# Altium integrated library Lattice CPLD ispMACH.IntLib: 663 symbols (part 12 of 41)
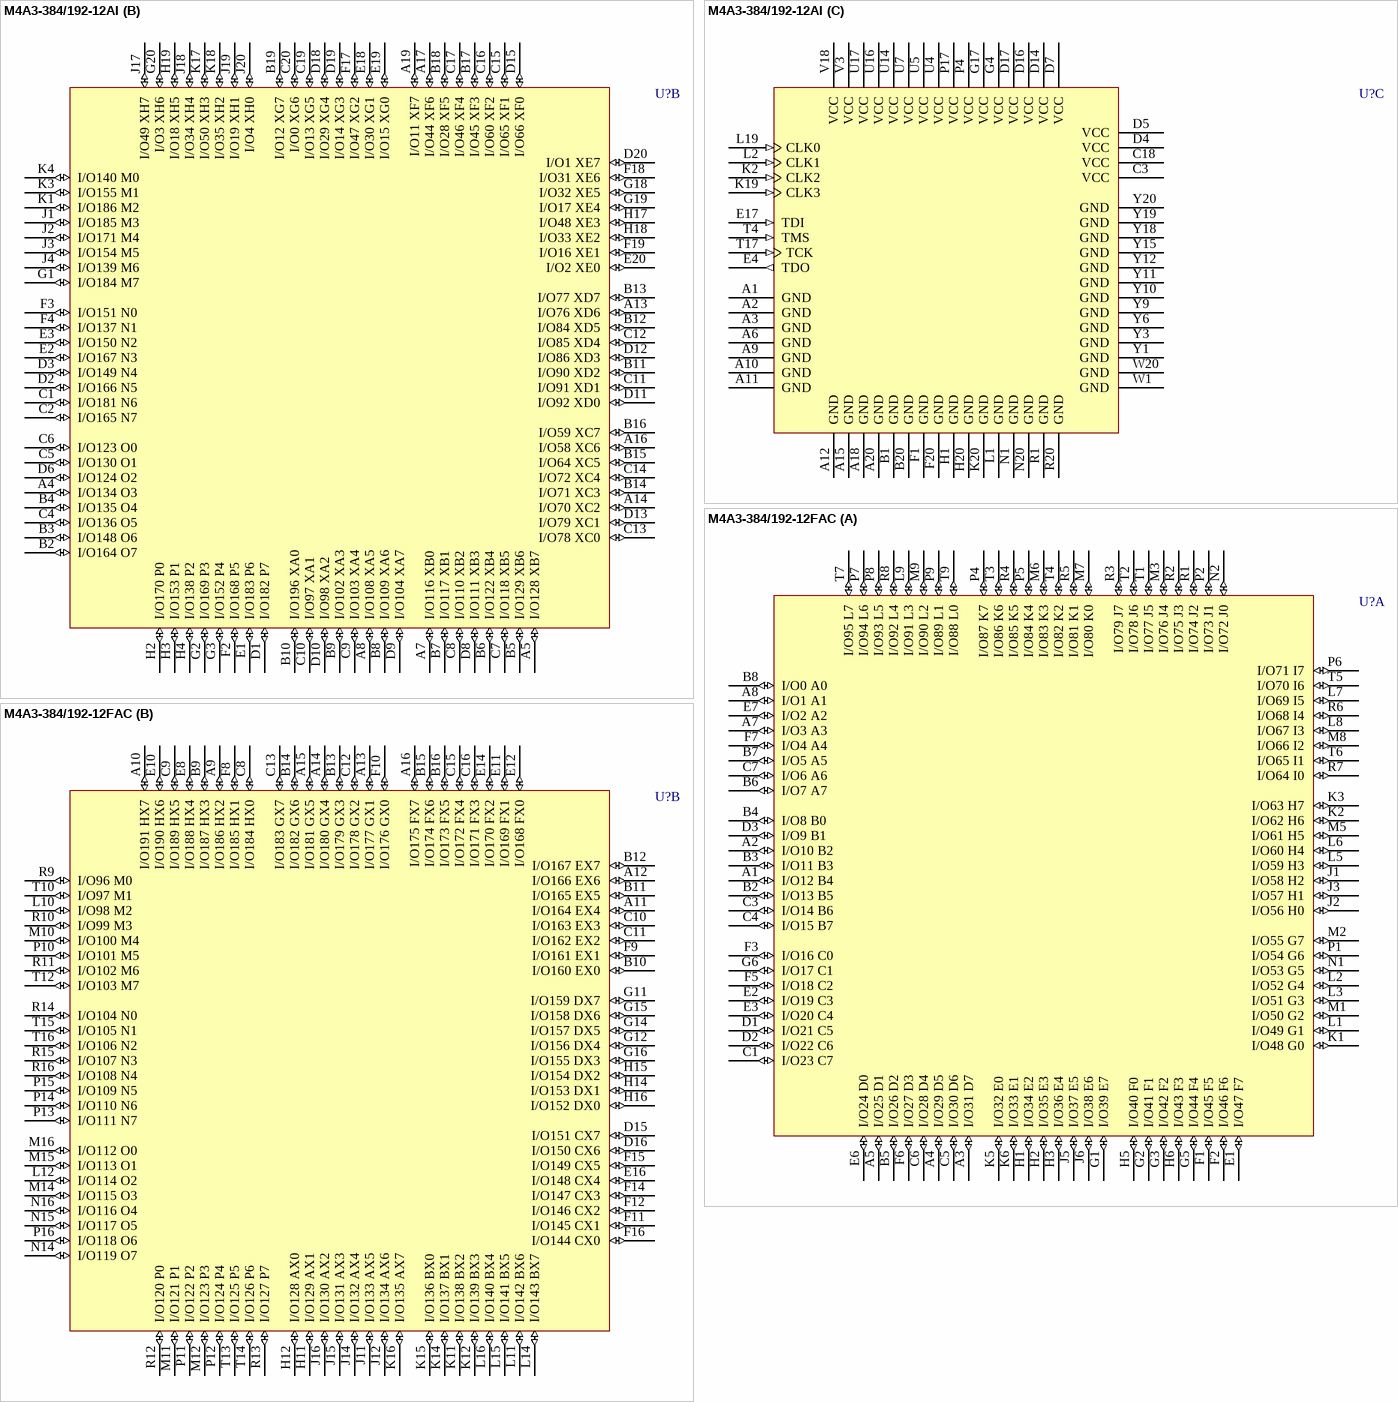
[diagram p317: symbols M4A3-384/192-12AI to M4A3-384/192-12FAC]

## M4A3-384/192-12AI
designator U?
High-Performance EE CMOS In-System Programmable Logic
footprint SBGA256 (BGA, 256-Leads, Body 27x27mm, Pitch 1.27mm)
3D model M4A3-SBGA256 (256-Ball Super Ball Grid Array (SBGA256))
part A pins: L3 I/O156 L4 (io), L4 I/O141 L3 (io), L17 I/O51 A1 (io), L18 I/O36 A0 (io), L20 I/O5 A2 (io), M1 I/O187 L1 (io), M2 I/O172 L0 (io), M3 I/O157 L5 (io), M4 I/O142 L6 (io), M17 I/O52 A6 (io), M18 I/O37 A5 (io), M19 I/O20 A3 (io), M20 I/O6 A4 (io), N2 I/O173 L7 (io), N3 I/O158 I0 (io), N4 I/O143 I5 (io), N17 I/O53 D1 (io), N18 I/O38 D0 (io), N19 I/O21 A7 (io), P1 I/O188 L2 (io), P2 I/O174 I1 (io), P3 I/O159 I4 (io), P18 I/O39 D4 (io), P19 I/O22 D3 (io), P20 I/O7 D2 (io), R2 I/O175 I3 (io), R3 I/O160 K0 (io), R4 I/O144 K5 (io), R17 I/O54 D7 (io), R18 I/O40 D6 (io), R19 I/O23 D5 (io), T1 I/O189 I2 (io), T2 I/O176 K1 (io), T3 I/O161 K4 (io), T18 I/O41 B7 (io), T19 I/O24 B0 (io), T20 I/O8 B3 (io), U1 I/O190 I6 (io), U2 I/O177 K2 (io), U3 I/O162 K7 (io), U6 I/O125 J1 (io), U8 I/O112 G0 (io), U9 I/O105 H5 (io), U10 I/O99 H2 (io), U11 I/O93 E2 (io), U12 I/O87 E5 (io), U13 I/O80 F0 (io), U15 I/O67 C0 (io), U18 I/O42 B6 (io), U19 I/O25 B1 (io), U20 I/O9 B4 (io), V1 I/O191 I7 (io), V2 I/O178 K3 (io), V4 I/O145 J5 (io), V5 I/O131 J2 (io), V6 I/O126 J0 (io), V7 I/O119 G4 (io), V8 I/O113 G1 (io), V9 I/O106 H4 (io), V10 I/O100 H1 (io), V11 I/O94 E1 (io), V12 I/O88 E4 (io), V13 I/O81 F1 (io), V14 I/O73 F4 (io), V15 I/O68 C1 (io), V16 I/O61 C2 (io), V17 I/O55 C5 (io), V19 I/O26 B2 (io), V20 I/O10 B5 (io), W2 I/O179 J7 (io), W3 I/O163 J6 (io), W4 I/O146 J4 (io), W5 I/O132 G7 (io), W6 I/O127 G5 (io), W7 I/O120 G3 (io), W8 I/O114 H7 (io), W9 I/O107 H3 (io), W10 I/O101 H0 (io), W11 I/O95 E0 (io), W12 I/O89 E3 (io), W13 I/O82 E7 (io), W14 I/O74 F3 (io), W15 I/O69 F5 (io), W16 I/O62 F7 (io), W17 I/O56 C3 (io), W18 I/O43 C6 (io), W19 I/O27 C7 (io), Y2 I/O180 K6 (io), Y4 I/O147 J3 (io), Y5 I/O133 G6 (io), Y7 I/O121 G2 (io), Y8 I/O115 H6 (io), Y13 I/O83 E6 (io), Y14 I/O75 F2 (io), Y16 I/O63 F6 (io), Y17 I/O57 C4 (io)
part B pins: A4 I/O134 O3 (io), A5 I/O128 XB7 (io), A7 I/O116 XB0 (io), A8 I/O108 XA5 (io), A13 I/O76 XD6 (io), A14 I/O70 XC2 (io), A16 I/O58 XC6 (io), A17 I/O44 XF6 (io), A19 I/O11 XF7 (io), B2 I/O164 O7 (io), B3 I/O148 O6 (io), B4 I/O135 O4 (io), B5 I/O129 XB6 (io), B6 I/O122 XB4 (io), B7 I/O117 XB1 (io), B8 I/O109 XA6 (io), B9 I/O102 XA3 (io), B10 I/O196 XA0 (io), B11 I/O90 XD2 (io), B12 I/O84 XD5 (io), B13 I/O77 XD7 (io), B14 I/O71 XC3 (io), B15 I/O64 XC5 (io), B16 I/O59 XC7 (io), B17 I/O45 XF3 (io), B18 I/O28 XF5 (io), B19 I/O12 XG7 (io), C1 I/O181 N6 (io), C2 I/O165 N7 (io), C4 I/O136 O5 (io), C5 I/O130 O1 (io), C6 I/O123 O0 (io), C7 I/O118 XB5 (io), C8 I/O110 XB2 (io), C9 I/O103 XA4 (io), C10 I/O97 XA1 (io), C11 I/O91 XD1 (io), C12 I/O85 XD4 (io), C13 I/O78 XC0 (io), C14 I/O72 XC4 (io), C15 I/O65 XF1 (io), C16 I/O60 XF2 (io), C17 I/O46 XF4 (io), C19 I/O13 XG5 (io), C20 I/O0 XG6 (io), D1 I/O182 P7 (io), D2 I/O166 N5 (io), D3 I/O149 N4 (io), D6 I/O124 O2 (io), D8 I/O111 XB3 (io), D9 I/O104 XA7 (io), D10 I/O98 XA2 (io), D11 I/O92 XD0 (io), D12 I/O86 XD3 (io), D13 I/O79 XC1 (io), D15 I/O66 XF0 (io), D18 I/O29 XG4 (io), D19 I/O14 XG3 (io), D20 I/O1 XE7 (io), E1 I/O183 P6 (io), E2 I/O167 N3 (io), E3 I/O150 N2 (io), E18 I/O30 XG1 (io), E19 I/O15 XG0 (io), E20 I/O2 XE0 (io), F2 I/O168 P5 (io), F3 I/O151 N0 (io), F4 I/O137 N1 (io), F17 I/O47 XG2 (io), F18 I/O31 XE6 (io), F19 I/O16 XE1 (io), G1 I/O184 M7 (io), G2 I/O169 P3 (io), G3 I/O152 P4 (io), G18 I/O32 XE5 (io), G19 I/O17 XE4 (io), G20 I/O3 XH6 (io), H2 I/O170 P0 (io), H3 I/O153 P1 (io), H4 I/O138 P2 (io), H17 I/O48 XE3 (io), H18 I/O33 XE2 (io), H19 I/O18 XH5 (io), J1 I/O185 M3 (io), J2 I/O171 M4 (io), J3 I/O154 M5 (io), J4 I/O139 M6 (io), J17 I/O49 XH7 (io), J18 I/O34 XH4 (io), J19 I/O19 XH1 (io), J20 I/O4 XH0 (io), K1 I/O186 M2 (io), K3 I/O155 M1 (io), K4 I/O140 M0 (io), K17 I/O50 XH3 (io), K18 I/O35 XH2 (io)
part C pins: A1 GND (power), A2 GND (power), A3 GND (power), A6 GND (power), A9 GND (power), A10 GND (power), A11 GND (power), A12 GND (power), A15 GND (power), A18 GND (power), A20 GND (power), B1 GND (power), B20 GND (power), C3 VCC (power), C18 VCC (power), D4 VCC (power), D5 VCC (power), D7 VCC (power), D14 VCC (power), D16 VCC (power), D17 VCC (power), E4 TDO (out), E17 TDI (in), F1 GND (power), F20 GND (power), G4 VCC (power), G17 VCC (power), H1 GND (power), H20 GND (power), K2 CLK2 (in), K19 CLK3 (in), K20 GND (power), L1 GND (power), L2 CLK1 (in), L19 CLK0 (in), N1 GND (power), N20 GND (power), P4 VCC (power), P17 VCC (power), R1 GND (power), R20 GND (power), T4 TMS (in), T17 TCK (in), U4 VCC (power), U5 VCC (power), U7 VCC (power), U14 VCC (power), U16 VCC (power), U17 VCC (power), V3 VCC (power), V18 VCC (power), W1 GND (power), W20 GND (power), Y1 GND (power), Y3 GND (power), Y6 GND (power), Y9 GND (power), Y10 GND (power), Y11 GND (power), Y12 GND (power), Y15 GND (power), Y18 GND (power), Y19 GND (power), Y20 GND (power)

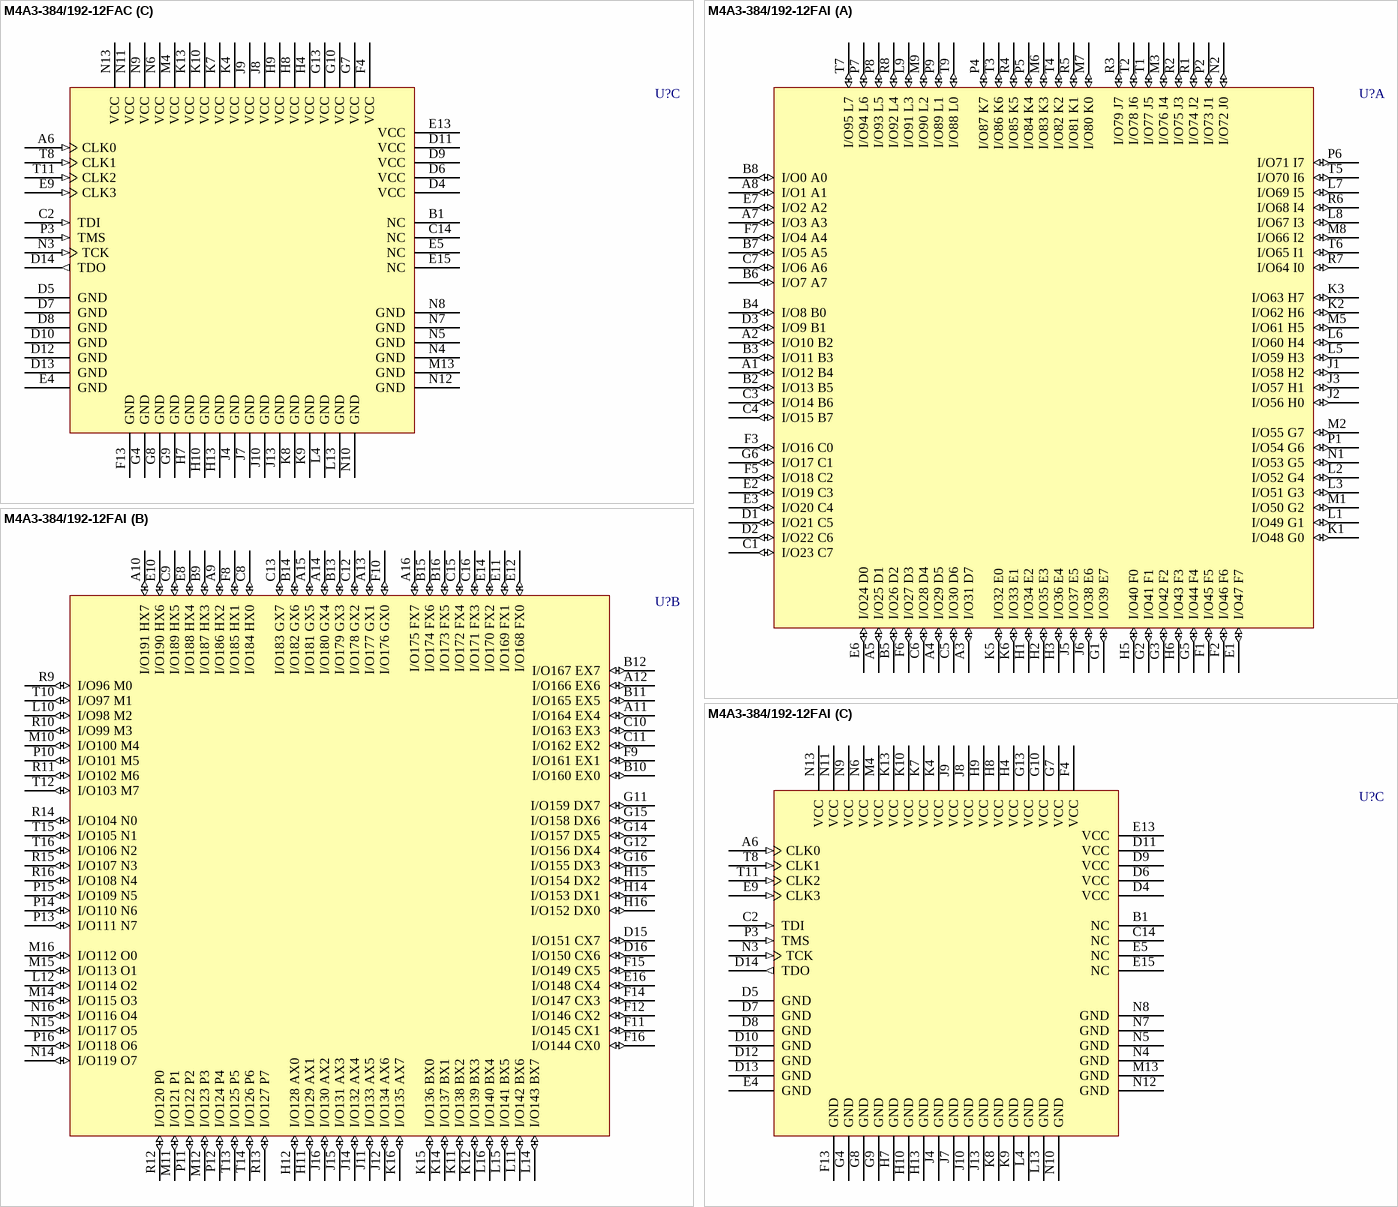
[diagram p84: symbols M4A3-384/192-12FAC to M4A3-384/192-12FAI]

## M4A3-384/192-12FAC
designator U?
High-Performance EE CMOS In-System Programmable Logic
footprint fpBGA256 (BGA, 256-Leads, Body 17x17mm, Pitch 1mm)
3D model M4A3-fpBGA256 (256-Ball Fine Pitch Ball Grid Array (fpBGA256))
part A pins: A1 I/O12 B4 (io), A2 I/O10 B2 (io), A3 I/O31 D7 (io), A4 I/O29 D5 (io), A5 I/O25 D1 (io), A7 I/O3 A3 (io), A8 I/O1 A1 (io), B2 I/O13 B5 (io), B3 I/O11 B3 (io), B4 I/O8 B0 (io), B5 I/O26 D2 (io), B6 I/O7 A7 (io), B7 I/O5 A5 (io), B8 I/O0 A0 (io), C1 I/O23 C7 (io), C3 I/O14 B6 (io), C4 I/O15 B7 (io), C5 I/O30 D6 (io), C6 I/O28 D4 (io), C7 I/O6 A6 (io), D1 I/O21 C5 (io), D2 I/O22 C6 (io), D3 I/O9 B1 (io), E1 I/O47 F7 (io), E2 I/O19 C3 (io), E3 I/O20 C4 (io), E6 I/O24 D0 (io), E7 I/O2 A2 (io), F1 I/O45 F5 (io), F2 I/O46 F6 (io), F3 I/O16 C0 (io), F5 I/O18 C2 (io), F6 I/O27 D3 (io), F7 I/O4 A4 (io), G1 I/O39 E7 (io), G2 I/O41 F1 (io), G3 I/O42 F2 (io), G5 I/O44 F4 (io), G6 I/O17 C1 (io), H1 I/O34 E2 (io), H2 I/O35 E3 (io), H3 I/O36 E4 (io), H5 I/O40 F0 (io), H6 I/O43 F3 (io), J1 I/O58 H2 (io), J2 I/O56 H0 (io), J3 I/O57 H1 (io), J5 I/O37 E5 (io), J6 I/O38 E6 (io), K1 I/O48 G0 (io), K2 I/O62 H6 (io), K3 I/O63 H7 (io), K5 I/O32 E0 (io), K6 I/O33 E1 (io), L1 I/O49 G1 (io), L2 I/O52 G4 (io), L3 I/O51 G3 (io), L5 I/O59 H3 (io), L6 I/O60 H4 (io), L7 I/O69 I5 (io), L8 I/O67 I3 (io), L9 I/O91 L3 (io), M1 I/O50 G2 (io), M2 I/O55 G7 (io), M3 I/O76 J4 (io), M5 I/O61 H5 (io), M6 I/O83 K3 (io), M7 I/O80 K0 (io), M8 I/O66 I2 (io), M9 I/O90 L2 (io), N1 I/O53 G5 (io), N2 I/O72 J0 (io), P1 I/O54 G6 (io), P2 I/O73 J1 (io), P4 I/O87 K7 (io), P5 I/O84 K4 (io), P6 I/O71 I7 (io), P7 I/O94 L6 (io), P8 I/O93 L5 (io), P9 I/O89 L1 (io), R1 I/O74 J2 (io), R2 I/O75 J3 (io), R3 I/O79 J7 (io), R4 I/O85 K5 (io), R5 I/O81 K1 (io), R6 I/O68 I4 (io), R7 I/O64 I0 (io), R8 I/O92 L4 (io), T1 I/O77 J5 (io), T2 I/O78 J6 (io), T3 I/O86 K6 (io), T4 I/O82 K2 (io), T5 I/O70 I6 (io), T6 I/O65 I1 (io), T7 I/O95 L7 (io), T9 I/O88 L0 (io)
part B pins: A9 I/O186 HX2 (io), A10 I/O191 HX7 (io), A11 I/O164 EX4 (io), A12 I/O166 EX6 (io), A13 I/O177 GX1 (io), A14 I/O180 GX4 (io), A15 I/O181 GX5 (io), A16 I/O175 FX7 (io), B9 I/O187 HX3 (io), B10 I/O160 EX0 (io), B11 I/O165 EX5 (io), B12 I/O167 EX7 (io), B13 I/O179 GX3 (io), B14 I/O182 GX6 (io), B15 I/O174 FX6 (io), B16 I/O173 FX5 (io), C8 I/O184 HX0 (io), C9 I/O189 HX5 (io), C10 I/O163 EX3 (io), C11 I/O162 EX2 (io), C12 I/O178 GX2 (io), C13 I/O183 GX7 (io), C15 I/O172 FX4 (io), C16 I/O171 FX3 (io), D15 I/O151 CX7 (io), D16 I/O150 CX6 (io), E8 I/O188 HX4 (io), E10 I/O190 HX6 (io), E11 I/O169 FX1 (io), E12 I/O168 FX0 (io), E14 I/O170 FX2 (io), E16 I/O148 CX4 (io), F8 I/O185 HX1 (io), F9 I/O161 EX1 (io), F10 I/O176 GX0 (io), F11 I/O145 CX1 (io), F12 I/O146 CX2 (io), F14 I/O147 CX3 (io), F15 I/O149 CX5 (io), F16 I/O144 CX0 (io), G11 I/O159 DX7 (io), G12 I/O156 DX4 (io), G14 I/O157 DX5 (io), G15 I/O158 DX6 (io), G16 I/O155 DX3 (io), H11 I/O129 AX1 (io), H12 I/O128 AX0 (io), H14 I/O153 DX1 (io), H15 I/O154 DX2 (io), H16 I/O152 DX0 (io), J11 I/O133 AX5 (io), J12 I/O134 AX6 (io), J14 I/O132 AX4 (io), J15 I/O131 AX3 (io), J16 I/O130 AX2 (io), K11 I/O138 BX2 (io), K12 I/O139 BX3 (io), K14 I/O137 BX1 (io), K15 I/O136 BX0 (io), K16 I/O135 AX7 (io), L10 I/O98 M2 (io), L11 I/O142 BX6 (io), L12 I/O114 O2 (io), L14 I/O143 BX7 (io), L15 I/O141 BX5 (io), L16 I/O140 BX4 (io), M10 I/O100 M4 (io), M11 I/O121 P1 (io), M12 I/O123 P3 (io), M14 I/O115 O3 (io), M15 I/O113 O1 (io), M16 I/O112 O0 (io), N14 I/O119 O7 (io), N15 I/O117 O5 (io), N16 I/O116 O4 (io), P10 I/O101 M5 (io), P11 I/O122 P2 (io), P12 I/O124 P4 (io), P13 I/O111 N7 (io), P14 I/O110 N6 (io), P15 I/O109 N5 (io), P16 I/O118 O6 (io), R9 I/O96 M0 (io), R10 I/O99 M3 (io), R11 I/O102 M6 (io), R12 I/O120 P0 (io), R13 I/O127 P7 (io), R14 I/O104 N0 (io), R15 I/O107 N3 (io), R16 I/O108 N4 (io), T10 I/O97 M1 (io), T12 I/O103 M7 (io), T13 I/O125 P5 (io), T14 I/O126 P6 (io), T15 I/O105 N1 (io), T16 I/O106 N2 (io)
part C pins: A6 CLK0 (in), B1 NC, C2 TDI (in), C14 NC, D4 VCC (power), D5 GND (power), D6 VCC (power), D7 GND (power), D8 GND (power), D9 VCC (power), D10 GND (power), D11 VCC (power), D12 GND (power), D13 GND (power), D14 TDO (out), E4 GND (power), E5 NC, E9 CLK3 (in), E13 VCC (power), E15 NC, F4 VCC (power), F13 GND (power), G4 GND (power), G7 VCC (power), G8 GND (power), G9 GND (power), G10 VCC (power), G13 VCC (power), H4 VCC (power), H7 GND (power), H8 VCC (power), H9 VCC (power), H10 GND (power), H13 GND (power), J4 GND (power), J7 GND (power), J8 VCC (power), J9 VCC (power), J10 GND (power), J13 GND (power), K4 VCC (power), K7 VCC (power), K8 GND (power), K9 GND (power), K10 VCC (power), K13 VCC (power), L4 GND (power), L13 GND (power), M4 VCC (power), M13 GND (power), N3 TCK (in), N4 GND (power), N5 GND (power), N6 VCC (power), N7 GND (power), N8 GND (power), N9 VCC (power), N10 GND (power), N11 VCC (power), N12 GND (power), N13 VCC (power), P3 TMS (in), T8 CLK1 (in), T11 CLK2 (in)

## M4A3-384/192-12FAI
designator U?
High-Performance EE CMOS In-System Programmable Logic
footprint fpBGA256 (BGA, 256-Leads, Body 17x17mm, Pitch 1mm)
3D model M4A3-fpBGA256 (256-Ball Fine Pitch Ball Grid Array (fpBGA256))
part A pins: A1 I/O12 B4 (io), A2 I/O10 B2 (io), A3 I/O31 D7 (io), A4 I/O29 D5 (io), A5 I/O25 D1 (io), A7 I/O3 A3 (io), A8 I/O1 A1 (io), B2 I/O13 B5 (io), B3 I/O11 B3 (io), B4 I/O8 B0 (io), B5 I/O26 D2 (io), B6 I/O7 A7 (io), B7 I/O5 A5 (io), B8 I/O0 A0 (io), C1 I/O23 C7 (io), C3 I/O14 B6 (io), C4 I/O15 B7 (io), C5 I/O30 D6 (io), C6 I/O28 D4 (io), C7 I/O6 A6 (io), D1 I/O21 C5 (io), D2 I/O22 C6 (io), D3 I/O9 B1 (io), E1 I/O47 F7 (io), E2 I/O19 C3 (io), E3 I/O20 C4 (io), E6 I/O24 D0 (io), E7 I/O2 A2 (io), F1 I/O45 F5 (io), F2 I/O46 F6 (io), F3 I/O16 C0 (io), F5 I/O18 C2 (io), F6 I/O27 D3 (io), F7 I/O4 A4 (io), G1 I/O39 E7 (io), G2 I/O41 F1 (io), G3 I/O42 F2 (io), G5 I/O44 F4 (io), G6 I/O17 C1 (io), H1 I/O34 E2 (io), H2 I/O35 E3 (io), H3 I/O36 E4 (io), H5 I/O40 F0 (io), H6 I/O43 F3 (io), J1 I/O58 H2 (io), J2 I/O56 H0 (io), J3 I/O57 H1 (io), J5 I/O37 E5 (io), J6 I/O38 E6 (io), K1 I/O48 G0 (io), K2 I/O62 H6 (io), K3 I/O63 H7 (io), K5 I/O32 E0 (io), K6 I/O33 E1 (io), L1 I/O49 G1 (io), L2 I/O52 G4 (io), L3 I/O51 G3 (io), L5 I/O59 H3 (io), L6 I/O60 H4 (io), L7 I/O69 I5 (io), L8 I/O67 I3 (io), L9 I/O91 L3 (io), M1 I/O50 G2 (io), M2 I/O55 G7 (io), M3 I/O76 J4 (io), M5 I/O61 H5 (io), M6 I/O83 K3 (io), M7 I/O80 K0 (io), M8 I/O66 I2 (io), M9 I/O90 L2 (io), N1 I/O53 G5 (io), N2 I/O72 J0 (io), P1 I/O54 G6 (io), P2 I/O73 J1 (io), P4 I/O87 K7 (io), P5 I/O84 K4 (io), P6 I/O71 I7 (io), P7 I/O94 L6 (io), P8 I/O93 L5 (io), P9 I/O89 L1 (io), R1 I/O74 J2 (io), R2 I/O75 J3 (io), R3 I/O79 J7 (io), R4 I/O85 K5 (io), R5 I/O81 K1 (io), R6 I/O68 I4 (io), R7 I/O64 I0 (io), R8 I/O92 L4 (io), T1 I/O77 J5 (io), T2 I/O78 J6 (io), T3 I/O86 K6 (io), T4 I/O82 K2 (io), T5 I/O70 I6 (io), T6 I/O65 I1 (io), T7 I/O95 L7 (io), T9 I/O88 L0 (io)
part B pins: A9 I/O186 HX2 (io), A10 I/O191 HX7 (io), A11 I/O164 EX4 (io), A12 I/O166 EX6 (io), A13 I/O177 GX1 (io), A14 I/O180 GX4 (io), A15 I/O181 GX5 (io), A16 I/O175 FX7 (io), B9 I/O187 HX3 (io), B10 I/O160 EX0 (io), B11 I/O165 EX5 (io), B12 I/O167 EX7 (io), B13 I/O179 GX3 (io), B14 I/O182 GX6 (io), B15 I/O174 FX6 (io), B16 I/O173 FX5 (io), C8 I/O184 HX0 (io), C9 I/O189 HX5 (io), C10 I/O163 EX3 (io), C11 I/O162 EX2 (io), C12 I/O178 GX2 (io), C13 I/O183 GX7 (io), C15 I/O172 FX4 (io), C16 I/O171 FX3 (io), D15 I/O151 CX7 (io), D16 I/O150 CX6 (io), E8 I/O188 HX4 (io), E10 I/O190 HX6 (io), E11 I/O169 FX1 (io), E12 I/O168 FX0 (io), E14 I/O170 FX2 (io), E16 I/O148 CX4 (io), F8 I/O185 HX1 (io), F9 I/O161 EX1 (io), F10 I/O176 GX0 (io), F11 I/O145 CX1 (io), F12 I/O146 CX2 (io), F14 I/O147 CX3 (io), F15 I/O149 CX5 (io), F16 I/O144 CX0 (io), G11 I/O159 DX7 (io), G12 I/O156 DX4 (io), G14 I/O157 DX5 (io), G15 I/O158 DX6 (io), G16 I/O155 DX3 (io), H11 I/O129 AX1 (io), H12 I/O128 AX0 (io), H14 I/O153 DX1 (io), H15 I/O154 DX2 (io), H16 I/O152 DX0 (io), J11 I/O133 AX5 (io), J12 I/O134 AX6 (io), J14 I/O132 AX4 (io), J15 I/O131 AX3 (io), J16 I/O130 AX2 (io), K11 I/O138 BX2 (io), K12 I/O139 BX3 (io), K14 I/O137 BX1 (io), K15 I/O136 BX0 (io), K16 I/O135 AX7 (io), L10 I/O98 M2 (io), L11 I/O142 BX6 (io), L12 I/O114 O2 (io), L14 I/O143 BX7 (io), L15 I/O141 BX5 (io), L16 I/O140 BX4 (io), M10 I/O100 M4 (io), M11 I/O121 P1 (io), M12 I/O123 P3 (io), M14 I/O115 O3 (io), M15 I/O113 O1 (io), M16 I/O112 O0 (io), N14 I/O119 O7 (io), N15 I/O117 O5 (io), N16 I/O116 O4 (io), P10 I/O101 M5 (io), P11 I/O122 P2 (io), P12 I/O124 P4 (io), P13 I/O111 N7 (io), P14 I/O110 N6 (io), P15 I/O109 N5 (io), P16 I/O118 O6 (io), R9 I/O96 M0 (io), R10 I/O99 M3 (io), R11 I/O102 M6 (io), R12 I/O120 P0 (io), R13 I/O127 P7 (io), R14 I/O104 N0 (io), R15 I/O107 N3 (io), R16 I/O108 N4 (io), T10 I/O97 M1 (io), T12 I/O103 M7 (io), T13 I/O125 P5 (io), T14 I/O126 P6 (io), T15 I/O105 N1 (io), T16 I/O106 N2 (io)
part C pins: A6 CLK0 (in), B1 NC, C2 TDI (in), C14 NC, D4 VCC (power), D5 GND (power), D6 VCC (power), D7 GND (power), D8 GND (power), D9 VCC (power), D10 GND (power), D11 VCC (power), D12 GND (power), D13 GND (power), D14 TDO (out), E4 GND (power), E5 NC, E9 CLK3 (in), E13 VCC (power), E15 NC, F4 VCC (power), F13 GND (power), G4 GND (power), G7 VCC (power), G8 GND (power), G9 GND (power), G10 VCC (power), G13 VCC (power), H4 VCC (power), H7 GND (power), H8 VCC (power), H9 VCC (power), H10 GND (power), H13 GND (power), J4 GND (power), J7 GND (power), J8 VCC (power), J9 VCC (power), J10 GND (power), J13 GND (power), K4 VCC (power), K7 VCC (power), K8 GND (power), K9 GND (power), K10 VCC (power), K13 VCC (power), L4 GND (power), L13 GND (power), M4 VCC (power), M13 GND (power), N3 TCK (in), N4 GND (power), N5 GND (power), N6 VCC (power), N7 GND (power), N8 GND (power), N9 VCC (power), N10 GND (power), N11 VCC (power), N12 GND (power), N13 VCC (power), P3 TMS (in), T8 CLK1 (in), T11 CLK2 (in)

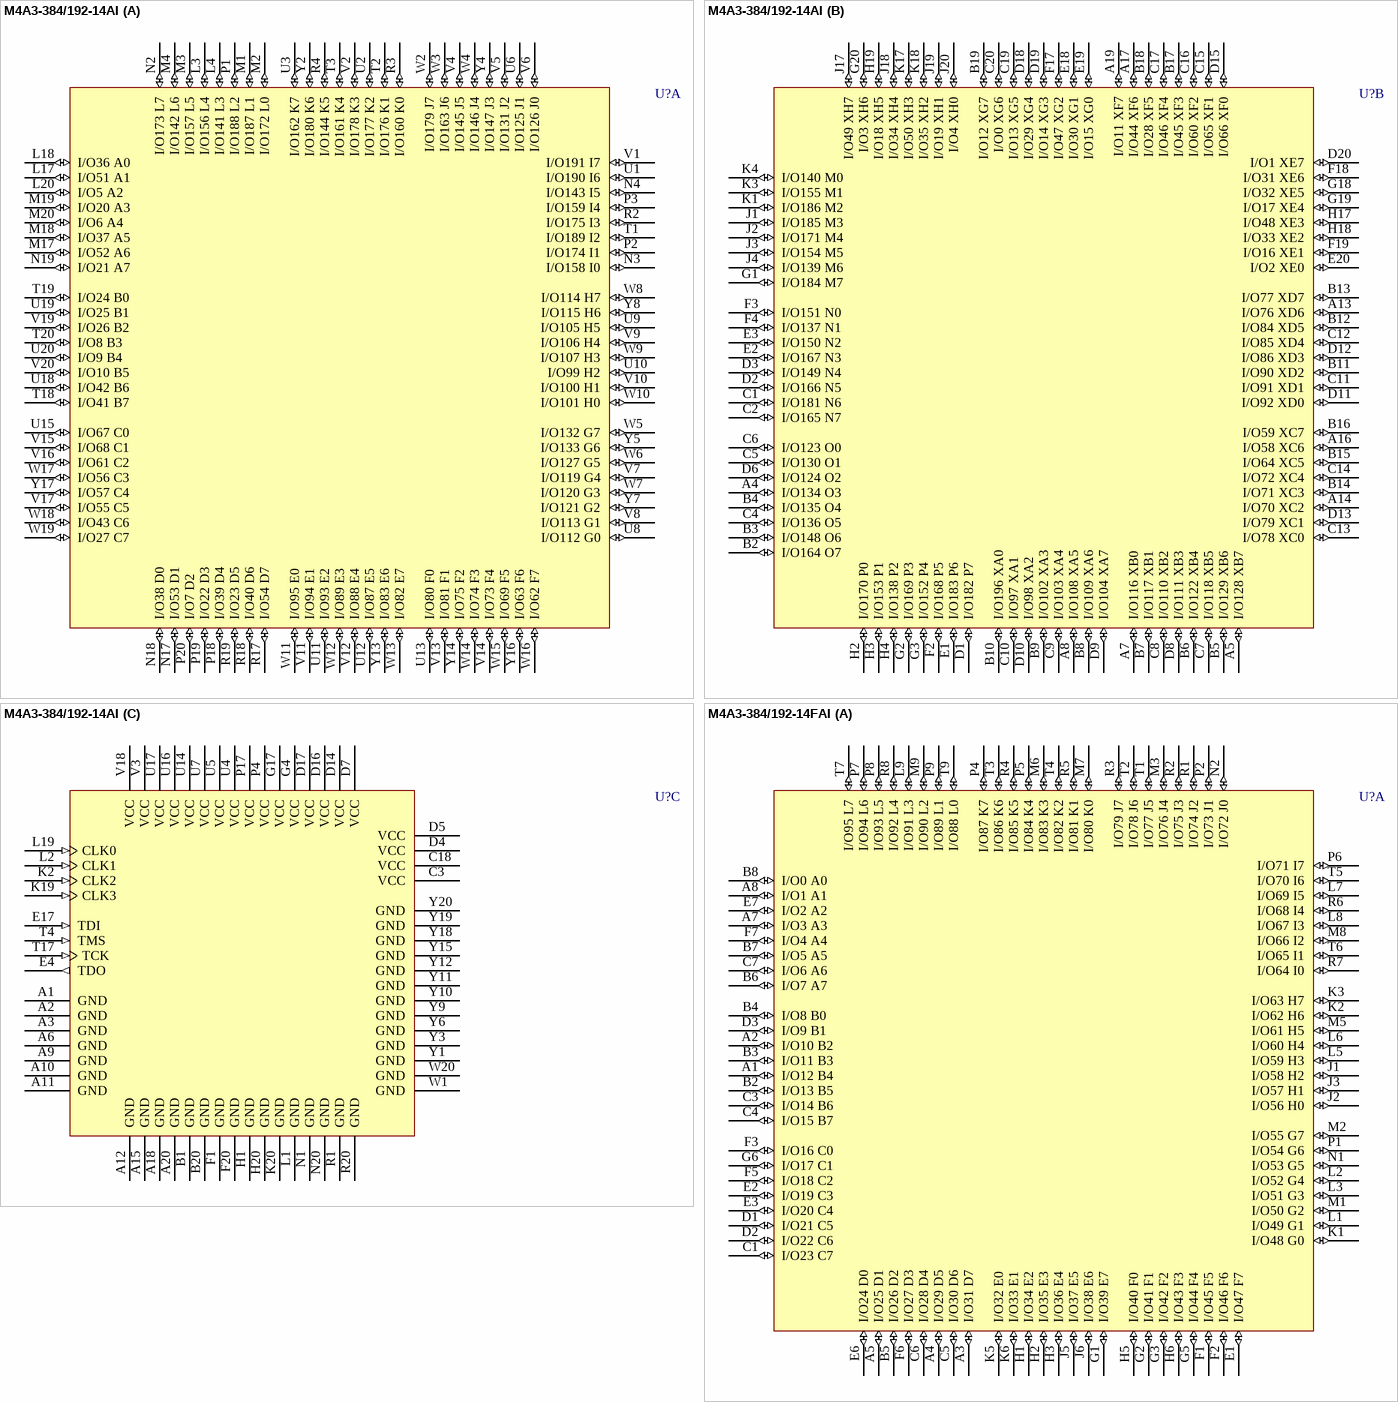
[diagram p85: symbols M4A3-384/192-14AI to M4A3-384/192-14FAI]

## M4A3-384/192-14AI
designator U?
High-Performance EE CMOS In-System Programmable Logic
footprint SBGA256 (BGA, 256-Leads, Body 27x27mm, Pitch 1.27mm)
3D model M4A3-SBGA256 (256-Ball Super Ball Grid Array (SBGA256))
part A pins: L3 I/O156 L4 (io), L4 I/O141 L3 (io), L17 I/O51 A1 (io), L18 I/O36 A0 (io), L20 I/O5 A2 (io), M1 I/O187 L1 (io), M2 I/O172 L0 (io), M3 I/O157 L5 (io), M4 I/O142 L6 (io), M17 I/O52 A6 (io), M18 I/O37 A5 (io), M19 I/O20 A3 (io), M20 I/O6 A4 (io), N2 I/O173 L7 (io), N3 I/O158 I0 (io), N4 I/O143 I5 (io), N17 I/O53 D1 (io), N18 I/O38 D0 (io), N19 I/O21 A7 (io), P1 I/O188 L2 (io), P2 I/O174 I1 (io), P3 I/O159 I4 (io), P18 I/O39 D4 (io), P19 I/O22 D3 (io), P20 I/O7 D2 (io), R2 I/O175 I3 (io), R3 I/O160 K0 (io), R4 I/O144 K5 (io), R17 I/O54 D7 (io), R18 I/O40 D6 (io), R19 I/O23 D5 (io), T1 I/O189 I2 (io), T2 I/O176 K1 (io), T3 I/O161 K4 (io), T18 I/O41 B7 (io), T19 I/O24 B0 (io), T20 I/O8 B3 (io), U1 I/O190 I6 (io), U2 I/O177 K2 (io), U3 I/O162 K7 (io), U6 I/O125 J1 (io), U8 I/O112 G0 (io), U9 I/O105 H5 (io), U10 I/O99 H2 (io), U11 I/O93 E2 (io), U12 I/O87 E5 (io), U13 I/O80 F0 (io), U15 I/O67 C0 (io), U18 I/O42 B6 (io), U19 I/O25 B1 (io), U20 I/O9 B4 (io), V1 I/O191 I7 (io), V2 I/O178 K3 (io), V4 I/O145 J5 (io), V5 I/O131 J2 (io), V6 I/O126 J0 (io), V7 I/O119 G4 (io), V8 I/O113 G1 (io), V9 I/O106 H4 (io), V10 I/O100 H1 (io), V11 I/O94 E1 (io), V12 I/O88 E4 (io), V13 I/O81 F1 (io), V14 I/O73 F4 (io), V15 I/O68 C1 (io), V16 I/O61 C2 (io), V17 I/O55 C5 (io), V19 I/O26 B2 (io), V20 I/O10 B5 (io), W2 I/O179 J7 (io), W3 I/O163 J6 (io), W4 I/O146 J4 (io), W5 I/O132 G7 (io), W6 I/O127 G5 (io), W7 I/O120 G3 (io), W8 I/O114 H7 (io), W9 I/O107 H3 (io), W10 I/O101 H0 (io), W11 I/O95 E0 (io), W12 I/O89 E3 (io), W13 I/O82 E7 (io), W14 I/O74 F3 (io), W15 I/O69 F5 (io), W16 I/O62 F7 (io), W17 I/O56 C3 (io), W18 I/O43 C6 (io), W19 I/O27 C7 (io), Y2 I/O180 K6 (io), Y4 I/O147 J3 (io), Y5 I/O133 G6 (io), Y7 I/O121 G2 (io), Y8 I/O115 H6 (io), Y13 I/O83 E6 (io), Y14 I/O75 F2 (io), Y16 I/O63 F6 (io), Y17 I/O57 C4 (io)
part B pins: A4 I/O134 O3 (io), A5 I/O128 XB7 (io), A7 I/O116 XB0 (io), A8 I/O108 XA5 (io), A13 I/O76 XD6 (io), A14 I/O70 XC2 (io), A16 I/O58 XC6 (io), A17 I/O44 XF6 (io), A19 I/O11 XF7 (io), B2 I/O164 O7 (io), B3 I/O148 O6 (io), B4 I/O135 O4 (io), B5 I/O129 XB6 (io), B6 I/O122 XB4 (io), B7 I/O117 XB1 (io), B8 I/O109 XA6 (io), B9 I/O102 XA3 (io), B10 I/O196 XA0 (io), B11 I/O90 XD2 (io), B12 I/O84 XD5 (io), B13 I/O77 XD7 (io), B14 I/O71 XC3 (io), B15 I/O64 XC5 (io), B16 I/O59 XC7 (io), B17 I/O45 XF3 (io), B18 I/O28 XF5 (io), B19 I/O12 XG7 (io), C1 I/O181 N6 (io), C2 I/O165 N7 (io), C4 I/O136 O5 (io), C5 I/O130 O1 (io), C6 I/O123 O0 (io), C7 I/O118 XB5 (io), C8 I/O110 XB2 (io), C9 I/O103 XA4 (io), C10 I/O97 XA1 (io), C11 I/O91 XD1 (io), C12 I/O85 XD4 (io), C13 I/O78 XC0 (io), C14 I/O72 XC4 (io), C15 I/O65 XF1 (io), C16 I/O60 XF2 (io), C17 I/O46 XF4 (io), C19 I/O13 XG5 (io), C20 I/O0 XG6 (io), D1 I/O182 P7 (io), D2 I/O166 N5 (io), D3 I/O149 N4 (io), D6 I/O124 O2 (io), D8 I/O111 XB3 (io), D9 I/O104 XA7 (io), D10 I/O98 XA2 (io), D11 I/O92 XD0 (io), D12 I/O86 XD3 (io), D13 I/O79 XC1 (io), D15 I/O66 XF0 (io), D18 I/O29 XG4 (io), D19 I/O14 XG3 (io), D20 I/O1 XE7 (io), E1 I/O183 P6 (io), E2 I/O167 N3 (io), E3 I/O150 N2 (io), E18 I/O30 XG1 (io), E19 I/O15 XG0 (io), E20 I/O2 XE0 (io), F2 I/O168 P5 (io), F3 I/O151 N0 (io), F4 I/O137 N1 (io), F17 I/O47 XG2 (io), F18 I/O31 XE6 (io), F19 I/O16 XE1 (io), G1 I/O184 M7 (io), G2 I/O169 P3 (io), G3 I/O152 P4 (io), G18 I/O32 XE5 (io), G19 I/O17 XE4 (io), G20 I/O3 XH6 (io), H2 I/O170 P0 (io), H3 I/O153 P1 (io), H4 I/O138 P2 (io), H17 I/O48 XE3 (io), H18 I/O33 XE2 (io), H19 I/O18 XH5 (io), J1 I/O185 M3 (io), J2 I/O171 M4 (io), J3 I/O154 M5 (io), J4 I/O139 M6 (io), J17 I/O49 XH7 (io), J18 I/O34 XH4 (io), J19 I/O19 XH1 (io), J20 I/O4 XH0 (io), K1 I/O186 M2 (io), K3 I/O155 M1 (io), K4 I/O140 M0 (io), K17 I/O50 XH3 (io), K18 I/O35 XH2 (io)
part C pins: A1 GND (power), A2 GND (power), A3 GND (power), A6 GND (power), A9 GND (power), A10 GND (power), A11 GND (power), A12 GND (power), A15 GND (power), A18 GND (power), A20 GND (power), B1 GND (power), B20 GND (power), C3 VCC (power), C18 VCC (power), D4 VCC (power), D5 VCC (power), D7 VCC (power), D14 VCC (power), D16 VCC (power), D17 VCC (power), E4 TDO (out), E17 TDI (in), F1 GND (power), F20 GND (power), G4 VCC (power), G17 VCC (power), H1 GND (power), H20 GND (power), K2 CLK2 (in), K19 CLK3 (in), K20 GND (power), L1 GND (power), L2 CLK1 (in), L19 CLK0 (in), N1 GND (power), N20 GND (power), P4 VCC (power), P17 VCC (power), R1 GND (power), R20 GND (power), T4 TMS (in), T17 TCK (in), U4 VCC (power), U5 VCC (power), U7 VCC (power), U14 VCC (power), U16 VCC (power), U17 VCC (power), V3 VCC (power), V18 VCC (power), W1 GND (power), W20 GND (power), Y1 GND (power), Y3 GND (power), Y6 GND (power), Y9 GND (power), Y10 GND (power), Y11 GND (power), Y12 GND (power), Y15 GND (power), Y18 GND (power), Y19 GND (power), Y20 GND (power)

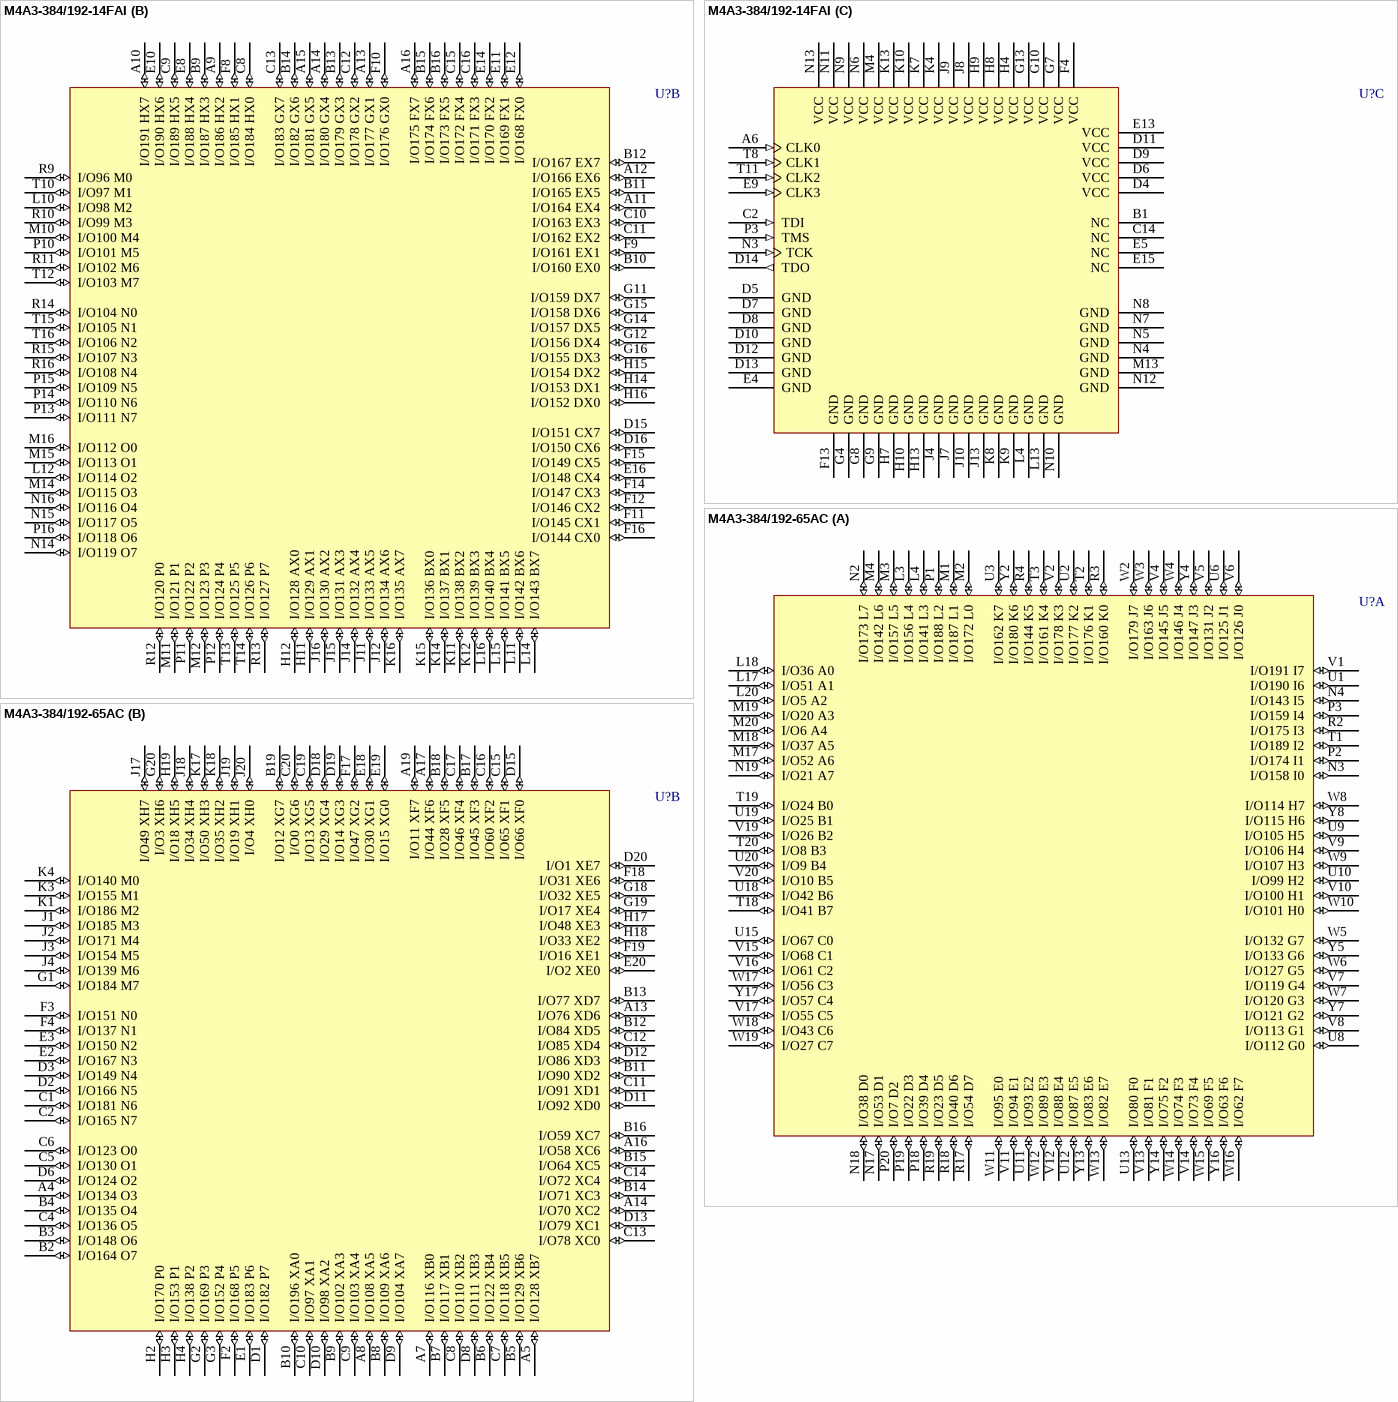
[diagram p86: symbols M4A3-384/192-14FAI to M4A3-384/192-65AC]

## M4A3-384/192-14FAI
designator U?
High-Performance EE CMOS In-System Programmable Logic
footprint fpBGA256 (BGA, 256-Leads, Body 17x17mm, Pitch 1mm)
3D model M4A3-fpBGA256 (256-Ball Fine Pitch Ball Grid Array (fpBGA256))
part A pins: A1 I/O12 B4 (io), A2 I/O10 B2 (io), A3 I/O31 D7 (io), A4 I/O29 D5 (io), A5 I/O25 D1 (io), A7 I/O3 A3 (io), A8 I/O1 A1 (io), B2 I/O13 B5 (io), B3 I/O11 B3 (io), B4 I/O8 B0 (io), B5 I/O26 D2 (io), B6 I/O7 A7 (io), B7 I/O5 A5 (io), B8 I/O0 A0 (io), C1 I/O23 C7 (io), C3 I/O14 B6 (io), C4 I/O15 B7 (io), C5 I/O30 D6 (io), C6 I/O28 D4 (io), C7 I/O6 A6 (io), D1 I/O21 C5 (io), D2 I/O22 C6 (io), D3 I/O9 B1 (io), E1 I/O47 F7 (io), E2 I/O19 C3 (io), E3 I/O20 C4 (io), E6 I/O24 D0 (io), E7 I/O2 A2 (io), F1 I/O45 F5 (io), F2 I/O46 F6 (io), F3 I/O16 C0 (io), F5 I/O18 C2 (io), F6 I/O27 D3 (io), F7 I/O4 A4 (io), G1 I/O39 E7 (io), G2 I/O41 F1 (io), G3 I/O42 F2 (io), G5 I/O44 F4 (io), G6 I/O17 C1 (io), H1 I/O34 E2 (io), H2 I/O35 E3 (io), H3 I/O36 E4 (io), H5 I/O40 F0 (io), H6 I/O43 F3 (io), J1 I/O58 H2 (io), J2 I/O56 H0 (io), J3 I/O57 H1 (io), J5 I/O37 E5 (io), J6 I/O38 E6 (io), K1 I/O48 G0 (io), K2 I/O62 H6 (io), K3 I/O63 H7 (io), K5 I/O32 E0 (io), K6 I/O33 E1 (io), L1 I/O49 G1 (io), L2 I/O52 G4 (io), L3 I/O51 G3 (io), L5 I/O59 H3 (io), L6 I/O60 H4 (io), L7 I/O69 I5 (io), L8 I/O67 I3 (io), L9 I/O91 L3 (io), M1 I/O50 G2 (io), M2 I/O55 G7 (io), M3 I/O76 J4 (io), M5 I/O61 H5 (io), M6 I/O83 K3 (io), M7 I/O80 K0 (io), M8 I/O66 I2 (io), M9 I/O90 L2 (io), N1 I/O53 G5 (io), N2 I/O72 J0 (io), P1 I/O54 G6 (io), P2 I/O73 J1 (io), P4 I/O87 K7 (io), P5 I/O84 K4 (io), P6 I/O71 I7 (io), P7 I/O94 L6 (io), P8 I/O93 L5 (io), P9 I/O89 L1 (io), R1 I/O74 J2 (io), R2 I/O75 J3 (io), R3 I/O79 J7 (io), R4 I/O85 K5 (io), R5 I/O81 K1 (io), R6 I/O68 I4 (io), R7 I/O64 I0 (io), R8 I/O92 L4 (io), T1 I/O77 J5 (io), T2 I/O78 J6 (io), T3 I/O86 K6 (io), T4 I/O82 K2 (io), T5 I/O70 I6 (io), T6 I/O65 I1 (io), T7 I/O95 L7 (io), T9 I/O88 L0 (io)
part B pins: A9 I/O186 HX2 (io), A10 I/O191 HX7 (io), A11 I/O164 EX4 (io), A12 I/O166 EX6 (io), A13 I/O177 GX1 (io), A14 I/O180 GX4 (io), A15 I/O181 GX5 (io), A16 I/O175 FX7 (io), B9 I/O187 HX3 (io), B10 I/O160 EX0 (io), B11 I/O165 EX5 (io), B12 I/O167 EX7 (io), B13 I/O179 GX3 (io), B14 I/O182 GX6 (io), B15 I/O174 FX6 (io), B16 I/O173 FX5 (io), C8 I/O184 HX0 (io), C9 I/O189 HX5 (io), C10 I/O163 EX3 (io), C11 I/O162 EX2 (io), C12 I/O178 GX2 (io), C13 I/O183 GX7 (io), C15 I/O172 FX4 (io), C16 I/O171 FX3 (io), D15 I/O151 CX7 (io), D16 I/O150 CX6 (io), E8 I/O188 HX4 (io), E10 I/O190 HX6 (io), E11 I/O169 FX1 (io), E12 I/O168 FX0 (io), E14 I/O170 FX2 (io), E16 I/O148 CX4 (io), F8 I/O185 HX1 (io), F9 I/O161 EX1 (io), F10 I/O176 GX0 (io), F11 I/O145 CX1 (io), F12 I/O146 CX2 (io), F14 I/O147 CX3 (io), F15 I/O149 CX5 (io), F16 I/O144 CX0 (io), G11 I/O159 DX7 (io), G12 I/O156 DX4 (io), G14 I/O157 DX5 (io), G15 I/O158 DX6 (io), G16 I/O155 DX3 (io), H11 I/O129 AX1 (io), H12 I/O128 AX0 (io), H14 I/O153 DX1 (io), H15 I/O154 DX2 (io), H16 I/O152 DX0 (io), J11 I/O133 AX5 (io), J12 I/O134 AX6 (io), J14 I/O132 AX4 (io), J15 I/O131 AX3 (io), J16 I/O130 AX2 (io), K11 I/O138 BX2 (io), K12 I/O139 BX3 (io), K14 I/O137 BX1 (io), K15 I/O136 BX0 (io), K16 I/O135 AX7 (io), L10 I/O98 M2 (io), L11 I/O142 BX6 (io), L12 I/O114 O2 (io), L14 I/O143 BX7 (io), L15 I/O141 BX5 (io), L16 I/O140 BX4 (io), M10 I/O100 M4 (io), M11 I/O121 P1 (io), M12 I/O123 P3 (io), M14 I/O115 O3 (io), M15 I/O113 O1 (io), M16 I/O112 O0 (io), N14 I/O119 O7 (io), N15 I/O117 O5 (io), N16 I/O116 O4 (io), P10 I/O101 M5 (io), P11 I/O122 P2 (io), P12 I/O124 P4 (io), P13 I/O111 N7 (io), P14 I/O110 N6 (io), P15 I/O109 N5 (io), P16 I/O118 O6 (io), R9 I/O96 M0 (io), R10 I/O99 M3 (io), R11 I/O102 M6 (io), R12 I/O120 P0 (io), R13 I/O127 P7 (io), R14 I/O104 N0 (io), R15 I/O107 N3 (io), R16 I/O108 N4 (io), T10 I/O97 M1 (io), T12 I/O103 M7 (io), T13 I/O125 P5 (io), T14 I/O126 P6 (io), T15 I/O105 N1 (io), T16 I/O106 N2 (io)
part C pins: A6 CLK0 (in), B1 NC, C2 TDI (in), C14 NC, D4 VCC (power), D5 GND (power), D6 VCC (power), D7 GND (power), D8 GND (power), D9 VCC (power), D10 GND (power), D11 VCC (power), D12 GND (power), D13 GND (power), D14 TDO (out), E4 GND (power), E5 NC, E9 CLK3 (in), E13 VCC (power), E15 NC, F4 VCC (power), F13 GND (power), G4 GND (power), G7 VCC (power), G8 GND (power), G9 GND (power), G10 VCC (power), G13 VCC (power), H4 VCC (power), H7 GND (power), H8 VCC (power), H9 VCC (power), H10 GND (power), H13 GND (power), J4 GND (power), J7 GND (power), J8 VCC (power), J9 VCC (power), J10 GND (power), J13 GND (power), K4 VCC (power), K7 VCC (power), K8 GND (power), K9 GND (power), K10 VCC (power), K13 VCC (power), L4 GND (power), L13 GND (power), M4 VCC (power), M13 GND (power), N3 TCK (in), N4 GND (power), N5 GND (power), N6 VCC (power), N7 GND (power), N8 GND (power), N9 VCC (power), N10 GND (power), N11 VCC (power), N12 GND (power), N13 VCC (power), P3 TMS (in), T8 CLK1 (in), T11 CLK2 (in)

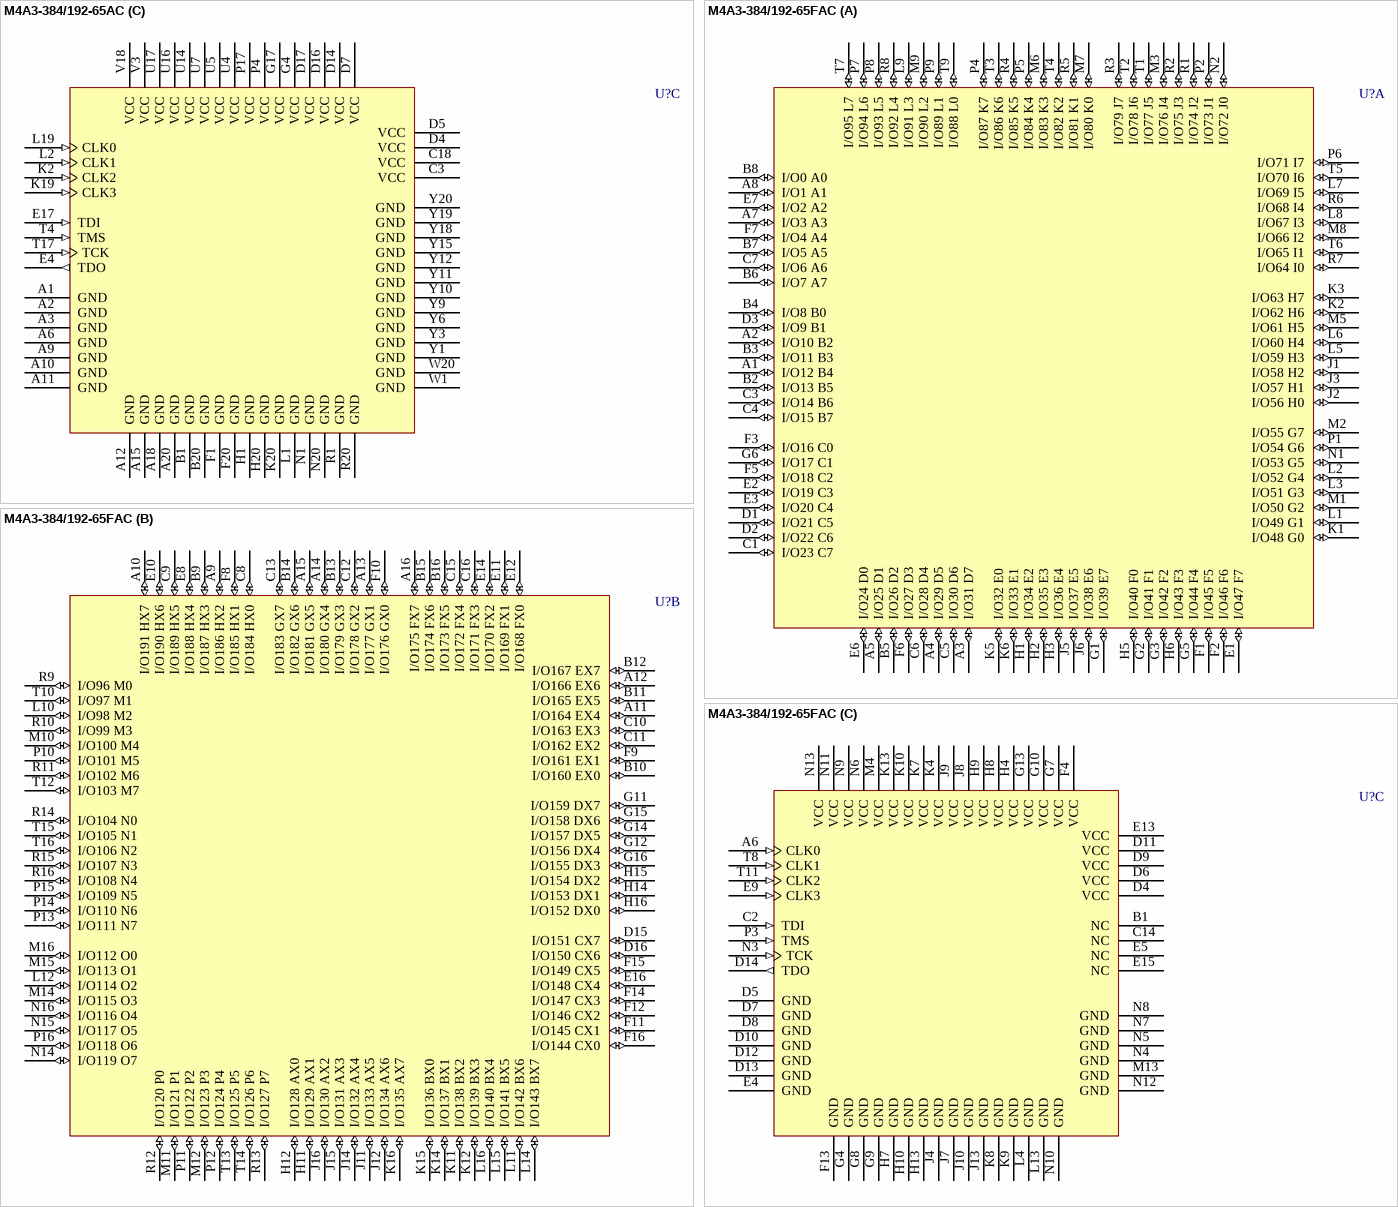
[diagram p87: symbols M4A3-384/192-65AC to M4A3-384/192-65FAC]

## M4A3-384/192-65AC
designator U?
High-Performance EE CMOS In-System Programmable Logic
footprint SBGA256 (BGA, 256-Leads, Body 27x27mm, Pitch 1.27mm)
3D model M4A3-SBGA256 (256-Ball Super Ball Grid Array (SBGA256))
part A pins: L3 I/O156 L4 (io), L4 I/O141 L3 (io), L17 I/O51 A1 (io), L18 I/O36 A0 (io), L20 I/O5 A2 (io), M1 I/O187 L1 (io), M2 I/O172 L0 (io), M3 I/O157 L5 (io), M4 I/O142 L6 (io), M17 I/O52 A6 (io), M18 I/O37 A5 (io), M19 I/O20 A3 (io), M20 I/O6 A4 (io), N2 I/O173 L7 (io), N3 I/O158 I0 (io), N4 I/O143 I5 (io), N17 I/O53 D1 (io), N18 I/O38 D0 (io), N19 I/O21 A7 (io), P1 I/O188 L2 (io), P2 I/O174 I1 (io), P3 I/O159 I4 (io), P18 I/O39 D4 (io), P19 I/O22 D3 (io), P20 I/O7 D2 (io), R2 I/O175 I3 (io), R3 I/O160 K0 (io), R4 I/O144 K5 (io), R17 I/O54 D7 (io), R18 I/O40 D6 (io), R19 I/O23 D5 (io), T1 I/O189 I2 (io), T2 I/O176 K1 (io), T3 I/O161 K4 (io), T18 I/O41 B7 (io), T19 I/O24 B0 (io), T20 I/O8 B3 (io), U1 I/O190 I6 (io), U2 I/O177 K2 (io), U3 I/O162 K7 (io), U6 I/O125 J1 (io), U8 I/O112 G0 (io), U9 I/O105 H5 (io), U10 I/O99 H2 (io), U11 I/O93 E2 (io), U12 I/O87 E5 (io), U13 I/O80 F0 (io), U15 I/O67 C0 (io), U18 I/O42 B6 (io), U19 I/O25 B1 (io), U20 I/O9 B4 (io), V1 I/O191 I7 (io), V2 I/O178 K3 (io), V4 I/O145 J5 (io), V5 I/O131 J2 (io), V6 I/O126 J0 (io), V7 I/O119 G4 (io), V8 I/O113 G1 (io), V9 I/O106 H4 (io), V10 I/O100 H1 (io), V11 I/O94 E1 (io), V12 I/O88 E4 (io), V13 I/O81 F1 (io), V14 I/O73 F4 (io), V15 I/O68 C1 (io), V16 I/O61 C2 (io), V17 I/O55 C5 (io), V19 I/O26 B2 (io), V20 I/O10 B5 (io), W2 I/O179 J7 (io), W3 I/O163 J6 (io), W4 I/O146 J4 (io), W5 I/O132 G7 (io), W6 I/O127 G5 (io), W7 I/O120 G3 (io), W8 I/O114 H7 (io), W9 I/O107 H3 (io), W10 I/O101 H0 (io), W11 I/O95 E0 (io), W12 I/O89 E3 (io), W13 I/O82 E7 (io), W14 I/O74 F3 (io), W15 I/O69 F5 (io), W16 I/O62 F7 (io), W17 I/O56 C3 (io), W18 I/O43 C6 (io), W19 I/O27 C7 (io), Y2 I/O180 K6 (io), Y4 I/O147 J3 (io), Y5 I/O133 G6 (io), Y7 I/O121 G2 (io), Y8 I/O115 H6 (io), Y13 I/O83 E6 (io), Y14 I/O75 F2 (io), Y16 I/O63 F6 (io), Y17 I/O57 C4 (io)
part B pins: A4 I/O134 O3 (io), A5 I/O128 XB7 (io), A7 I/O116 XB0 (io), A8 I/O108 XA5 (io), A13 I/O76 XD6 (io), A14 I/O70 XC2 (io), A16 I/O58 XC6 (io), A17 I/O44 XF6 (io), A19 I/O11 XF7 (io), B2 I/O164 O7 (io), B3 I/O148 O6 (io), B4 I/O135 O4 (io), B5 I/O129 XB6 (io), B6 I/O122 XB4 (io), B7 I/O117 XB1 (io), B8 I/O109 XA6 (io), B9 I/O102 XA3 (io), B10 I/O196 XA0 (io), B11 I/O90 XD2 (io), B12 I/O84 XD5 (io), B13 I/O77 XD7 (io), B14 I/O71 XC3 (io), B15 I/O64 XC5 (io), B16 I/O59 XC7 (io), B17 I/O45 XF3 (io), B18 I/O28 XF5 (io), B19 I/O12 XG7 (io), C1 I/O181 N6 (io), C2 I/O165 N7 (io), C4 I/O136 O5 (io), C5 I/O130 O1 (io), C6 I/O123 O0 (io), C7 I/O118 XB5 (io), C8 I/O110 XB2 (io), C9 I/O103 XA4 (io), C10 I/O97 XA1 (io), C11 I/O91 XD1 (io), C12 I/O85 XD4 (io), C13 I/O78 XC0 (io), C14 I/O72 XC4 (io), C15 I/O65 XF1 (io), C16 I/O60 XF2 (io), C17 I/O46 XF4 (io), C19 I/O13 XG5 (io), C20 I/O0 XG6 (io), D1 I/O182 P7 (io), D2 I/O166 N5 (io), D3 I/O149 N4 (io), D6 I/O124 O2 (io), D8 I/O111 XB3 (io), D9 I/O104 XA7 (io), D10 I/O98 XA2 (io), D11 I/O92 XD0 (io), D12 I/O86 XD3 (io), D13 I/O79 XC1 (io), D15 I/O66 XF0 (io), D18 I/O29 XG4 (io), D19 I/O14 XG3 (io), D20 I/O1 XE7 (io), E1 I/O183 P6 (io), E2 I/O167 N3 (io), E3 I/O150 N2 (io), E18 I/O30 XG1 (io), E19 I/O15 XG0 (io), E20 I/O2 XE0 (io), F2 I/O168 P5 (io), F3 I/O151 N0 (io), F4 I/O137 N1 (io), F17 I/O47 XG2 (io), F18 I/O31 XE6 (io), F19 I/O16 XE1 (io), G1 I/O184 M7 (io), G2 I/O169 P3 (io), G3 I/O152 P4 (io), G18 I/O32 XE5 (io), G19 I/O17 XE4 (io), G20 I/O3 XH6 (io), H2 I/O170 P0 (io), H3 I/O153 P1 (io), H4 I/O138 P2 (io), H17 I/O48 XE3 (io), H18 I/O33 XE2 (io), H19 I/O18 XH5 (io), J1 I/O185 M3 (io), J2 I/O171 M4 (io), J3 I/O154 M5 (io), J4 I/O139 M6 (io), J17 I/O49 XH7 (io), J18 I/O34 XH4 (io), J19 I/O19 XH1 (io), J20 I/O4 XH0 (io), K1 I/O186 M2 (io), K3 I/O155 M1 (io), K4 I/O140 M0 (io), K17 I/O50 XH3 (io), K18 I/O35 XH2 (io)
part C pins: A1 GND (power), A2 GND (power), A3 GND (power), A6 GND (power), A9 GND (power), A10 GND (power), A11 GND (power), A12 GND (power), A15 GND (power), A18 GND (power), A20 GND (power), B1 GND (power), B20 GND (power), C3 VCC (power), C18 VCC (power), D4 VCC (power), D5 VCC (power), D7 VCC (power), D14 VCC (power), D16 VCC (power), D17 VCC (power), E4 TDO (out), E17 TDI (in), F1 GND (power), F20 GND (power), G4 VCC (power), G17 VCC (power), H1 GND (power), H20 GND (power), K2 CLK2 (in), K19 CLK3 (in), K20 GND (power), L1 GND (power), L2 CLK1 (in), L19 CLK0 (in), N1 GND (power), N20 GND (power), P4 VCC (power), P17 VCC (power), R1 GND (power), R20 GND (power), T4 TMS (in), T17 TCK (in), U4 VCC (power), U5 VCC (power), U7 VCC (power), U14 VCC (power), U16 VCC (power), U17 VCC (power), V3 VCC (power), V18 VCC (power), W1 GND (power), W20 GND (power), Y1 GND (power), Y3 GND (power), Y6 GND (power), Y9 GND (power), Y10 GND (power), Y11 GND (power), Y12 GND (power), Y15 GND (power), Y18 GND (power), Y19 GND (power), Y20 GND (power)

## M4A3-384/192-65FAC
designator U?
High-Performance EE CMOS In-System Programmable Logic
footprint fpBGA256 (BGA, 256-Leads, Body 17x17mm, Pitch 1mm)
3D model M4A3-fpBGA256 (256-Ball Fine Pitch Ball Grid Array (fpBGA256))
part A pins: A1 I/O12 B4 (io), A2 I/O10 B2 (io), A3 I/O31 D7 (io), A4 I/O29 D5 (io), A5 I/O25 D1 (io), A7 I/O3 A3 (io), A8 I/O1 A1 (io), B2 I/O13 B5 (io), B3 I/O11 B3 (io), B4 I/O8 B0 (io), B5 I/O26 D2 (io), B6 I/O7 A7 (io), B7 I/O5 A5 (io), B8 I/O0 A0 (io), C1 I/O23 C7 (io), C3 I/O14 B6 (io), C4 I/O15 B7 (io), C5 I/O30 D6 (io), C6 I/O28 D4 (io), C7 I/O6 A6 (io), D1 I/O21 C5 (io), D2 I/O22 C6 (io), D3 I/O9 B1 (io), E1 I/O47 F7 (io), E2 I/O19 C3 (io), E3 I/O20 C4 (io), E6 I/O24 D0 (io), E7 I/O2 A2 (io), F1 I/O45 F5 (io), F2 I/O46 F6 (io), F3 I/O16 C0 (io), F5 I/O18 C2 (io), F6 I/O27 D3 (io), F7 I/O4 A4 (io), G1 I/O39 E7 (io), G2 I/O41 F1 (io), G3 I/O42 F2 (io), G5 I/O44 F4 (io), G6 I/O17 C1 (io), H1 I/O34 E2 (io), H2 I/O35 E3 (io), H3 I/O36 E4 (io), H5 I/O40 F0 (io), H6 I/O43 F3 (io), J1 I/O58 H2 (io), J2 I/O56 H0 (io), J3 I/O57 H1 (io), J5 I/O37 E5 (io), J6 I/O38 E6 (io), K1 I/O48 G0 (io), K2 I/O62 H6 (io), K3 I/O63 H7 (io), K5 I/O32 E0 (io), K6 I/O33 E1 (io), L1 I/O49 G1 (io), L2 I/O52 G4 (io), L3 I/O51 G3 (io), L5 I/O59 H3 (io), L6 I/O60 H4 (io), L7 I/O69 I5 (io), L8 I/O67 I3 (io), L9 I/O91 L3 (io), M1 I/O50 G2 (io), M2 I/O55 G7 (io), M3 I/O76 J4 (io), M5 I/O61 H5 (io), M6 I/O83 K3 (io), M7 I/O80 K0 (io), M8 I/O66 I2 (io), M9 I/O90 L2 (io), N1 I/O53 G5 (io), N2 I/O72 J0 (io), P1 I/O54 G6 (io), P2 I/O73 J1 (io), P4 I/O87 K7 (io), P5 I/O84 K4 (io), P6 I/O71 I7 (io), P7 I/O94 L6 (io), P8 I/O93 L5 (io), P9 I/O89 L1 (io), R1 I/O74 J2 (io), R2 I/O75 J3 (io), R3 I/O79 J7 (io), R4 I/O85 K5 (io), R5 I/O81 K1 (io), R6 I/O68 I4 (io), R7 I/O64 I0 (io), R8 I/O92 L4 (io), T1 I/O77 J5 (io), T2 I/O78 J6 (io), T3 I/O86 K6 (io), T4 I/O82 K2 (io), T5 I/O70 I6 (io), T6 I/O65 I1 (io), T7 I/O95 L7 (io), T9 I/O88 L0 (io)
part B pins: A9 I/O186 HX2 (io), A10 I/O191 HX7 (io), A11 I/O164 EX4 (io), A12 I/O166 EX6 (io), A13 I/O177 GX1 (io), A14 I/O180 GX4 (io), A15 I/O181 GX5 (io), A16 I/O175 FX7 (io), B9 I/O187 HX3 (io), B10 I/O160 EX0 (io), B11 I/O165 EX5 (io), B12 I/O167 EX7 (io), B13 I/O179 GX3 (io), B14 I/O182 GX6 (io), B15 I/O174 FX6 (io), B16 I/O173 FX5 (io), C8 I/O184 HX0 (io), C9 I/O189 HX5 (io), C10 I/O163 EX3 (io), C11 I/O162 EX2 (io), C12 I/O178 GX2 (io), C13 I/O183 GX7 (io), C15 I/O172 FX4 (io), C16 I/O171 FX3 (io), D15 I/O151 CX7 (io), D16 I/O150 CX6 (io), E8 I/O188 HX4 (io), E10 I/O190 HX6 (io), E11 I/O169 FX1 (io), E12 I/O168 FX0 (io), E14 I/O170 FX2 (io), E16 I/O148 CX4 (io), F8 I/O185 HX1 (io), F9 I/O161 EX1 (io), F10 I/O176 GX0 (io), F11 I/O145 CX1 (io), F12 I/O146 CX2 (io), F14 I/O147 CX3 (io), F15 I/O149 CX5 (io), F16 I/O144 CX0 (io), G11 I/O159 DX7 (io), G12 I/O156 DX4 (io), G14 I/O157 DX5 (io), G15 I/O158 DX6 (io), G16 I/O155 DX3 (io), H11 I/O129 AX1 (io), H12 I/O128 AX0 (io), H14 I/O153 DX1 (io), H15 I/O154 DX2 (io), H16 I/O152 DX0 (io), J11 I/O133 AX5 (io), J12 I/O134 AX6 (io), J14 I/O132 AX4 (io), J15 I/O131 AX3 (io), J16 I/O130 AX2 (io), K11 I/O138 BX2 (io), K12 I/O139 BX3 (io), K14 I/O137 BX1 (io), K15 I/O136 BX0 (io), K16 I/O135 AX7 (io), L10 I/O98 M2 (io), L11 I/O142 BX6 (io), L12 I/O114 O2 (io), L14 I/O143 BX7 (io), L15 I/O141 BX5 (io), L16 I/O140 BX4 (io), M10 I/O100 M4 (io), M11 I/O121 P1 (io), M12 I/O123 P3 (io), M14 I/O115 O3 (io), M15 I/O113 O1 (io), M16 I/O112 O0 (io), N14 I/O119 O7 (io), N15 I/O117 O5 (io), N16 I/O116 O4 (io), P10 I/O101 M5 (io), P11 I/O122 P2 (io), P12 I/O124 P4 (io), P13 I/O111 N7 (io), P14 I/O110 N6 (io), P15 I/O109 N5 (io), P16 I/O118 O6 (io), R9 I/O96 M0 (io), R10 I/O99 M3 (io), R11 I/O102 M6 (io), R12 I/O120 P0 (io), R13 I/O127 P7 (io), R14 I/O104 N0 (io), R15 I/O107 N3 (io), R16 I/O108 N4 (io), T10 I/O97 M1 (io), T12 I/O103 M7 (io), T13 I/O125 P5 (io), T14 I/O126 P6 (io), T15 I/O105 N1 (io), T16 I/O106 N2 (io)
part C pins: A6 CLK0 (in), B1 NC, C2 TDI (in), C14 NC, D4 VCC (power), D5 GND (power), D6 VCC (power), D7 GND (power), D8 GND (power), D9 VCC (power), D10 GND (power), D11 VCC (power), D12 GND (power), D13 GND (power), D14 TDO (out), E4 GND (power), E5 NC, E9 CLK3 (in), E13 VCC (power), E15 NC, F4 VCC (power), F13 GND (power), G4 GND (power), G7 VCC (power), G8 GND (power), G9 GND (power), G10 VCC (power), G13 VCC (power), H4 VCC (power), H7 GND (power), H8 VCC (power), H9 VCC (power), H10 GND (power), H13 GND (power), J4 GND (power), J7 GND (power), J8 VCC (power), J9 VCC (power), J10 GND (power), J13 GND (power), K4 VCC (power), K7 VCC (power), K8 GND (power), K9 GND (power), K10 VCC (power), K13 VCC (power), L4 GND (power), L13 GND (power), M4 VCC (power), M13 GND (power), N3 TCK (in), N4 GND (power), N5 GND (power), N6 VCC (power), N7 GND (power), N8 GND (power), N9 VCC (power), N10 GND (power), N11 VCC (power), N12 GND (power), N13 VCC (power), P3 TMS (in), T8 CLK1 (in), T11 CLK2 (in)

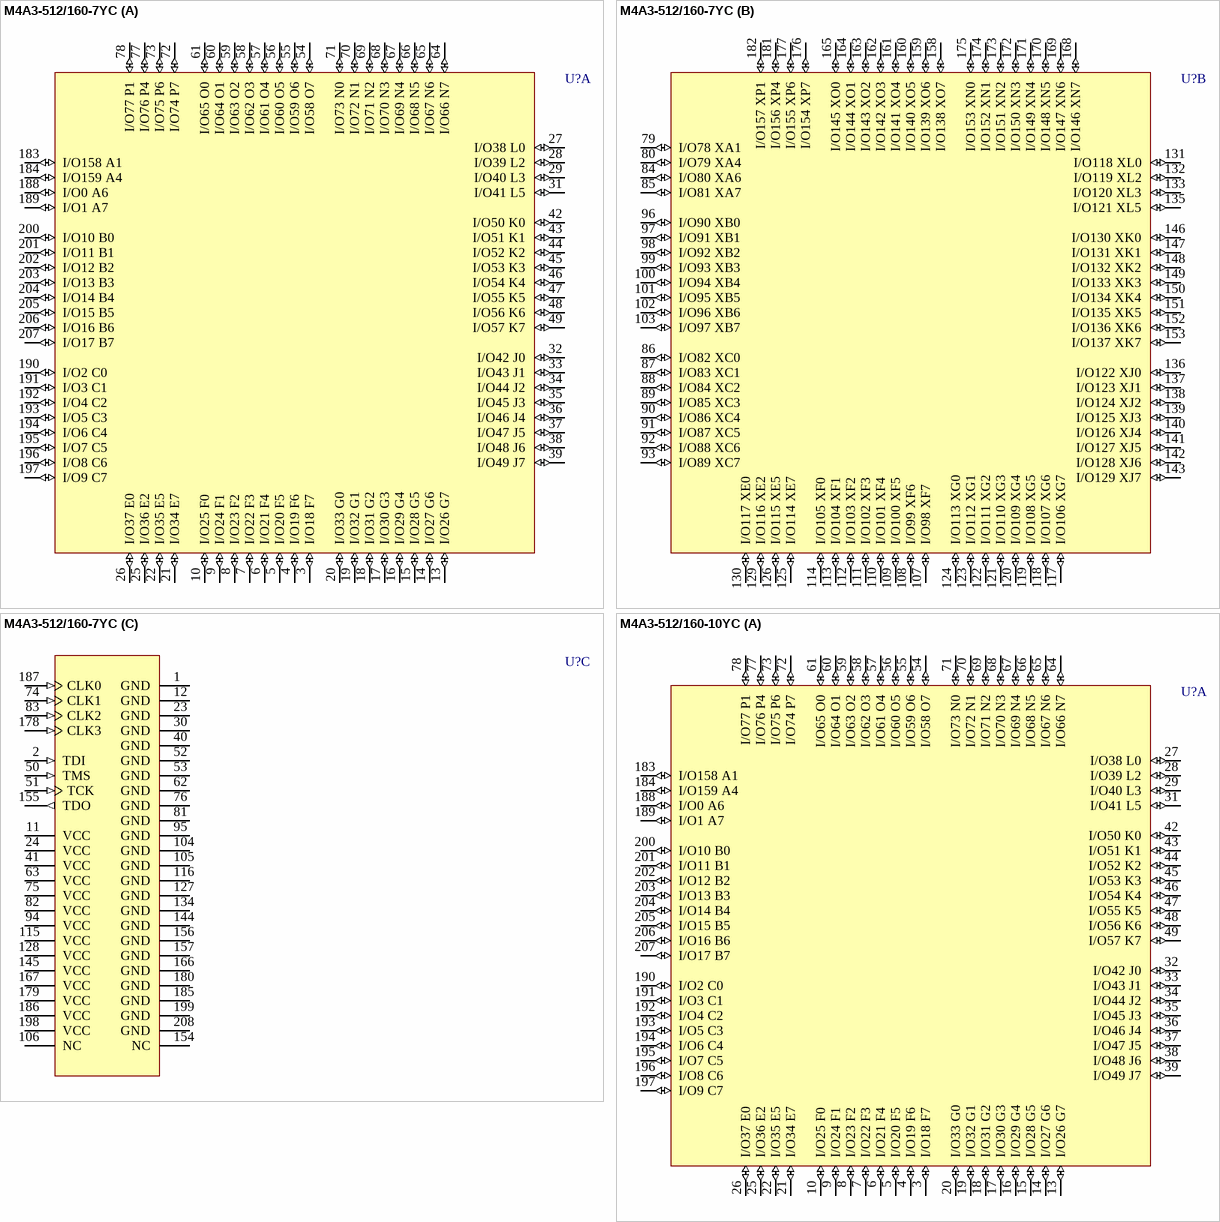
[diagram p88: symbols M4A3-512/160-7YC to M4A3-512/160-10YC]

## M4A3-512/160-7YC
designator U?
High-Performance EE CMOS In-System Programmable Logic
footprint PQFP208_N (Shrink QFP, 208-Leads, Body 28x28mm, Pitch 0.5mm, IPC Medium Density)
footprint PQFP208_L (Shrink QFP, 208-Leads, Body 28x28mm, Pitch 0.5mm, IPC High Density)
footprint PQFP208_M (Shrink QFP, 208-Leads, Body 28x28mm, Pitch 0.5mm, IPC Low Density)
3D model M4A3-PQFP208 (208-Pin Plastic Quad Flat Pack (PQFP208))
part A pins: 3 I/O18 F7 (io), 4 I/O19 F6 (io), 5 I/O20 F5 (io), 6 I/O21 F4 (io), 7 I/O22 F3 (io), 8 I/O23 F2 (io), 9 I/O24 F1 (io), 10 I/O25 F0 (io), 13 I/O26 G7 (io), 14 I/O27 G6 (io), 15 I/O28 G5 (io), 16 I/O29 G4 (io), 17 I/O30 G3 (io), 18 I/O31 G2 (io), 19 I/O32 G1 (io), 20 I/O33 G0 (io), 21 I/O34 E7 (io), 22 I/O35 E5 (io), 25 I/O36 E2 (io), 26 I/O37 E0 (io), 27 I/O38 L0 (io), 28 I/O39 L2 (io), 29 I/O40 L3 (io), 31 I/O41 L5 (io), 32 I/O42 J0 (io), 33 I/O43 J1 (io), 34 I/O44 J2 (io), 35 I/O45 J3 (io), 36 I/O46 J4 (io), 37 I/O47 J5 (io), 38 I/O48 J6 (io), 39 I/O49 J7 (io), 42 I/O50 K0 (io), 43 I/O51 K1 (io), 44 I/O52 K2 (io), 45 I/O53 K3 (io), 46 I/O54 K4 (io), 47 I/O55 K5 (io), 48 I/O56 K6 (io), 49 I/O57 K7 (io), 54 I/O58 O7 (io), 55 I/O59 O6 (io), 56 I/O60 O5 (io), 57 I/O61 O4 (io), 58 I/O62 O3 (io), 59 I/O63 O2 (io), 60 I/O64 O1 (io), 61 I/O65 O0 (io), 64 I/O66 N7 (io), 65 I/O67 N6 (io), 66 I/O68 N5 (io), 67 I/O69 N4 (io), 68 I/O70 N3 (io), 69 I/O71 N2 (io), 70 I/O72 N1 (io), 71 I/O73 N0 (io), 72 I/O74 P7 (io), 73 I/O75 P6 (io), 77 I/O76 P4 (io), 78 I/O77 P1 (io), 183 I/O158 A1 (io), 184 I/O159 A4 (io), 188 I/O0 A6 (io), 189 I/O1 A7 (io), 190 I/O2 C0 (io), 191 I/O3 C1 (io), 192 I/O4 C2 (io), 193 I/O5 C3 (io), 194 I/O6 C4 (io), 195 I/O7 C5 (io), 196 I/O8 C6 (io), 197 I/O9 C7 (io), 200 I/O10 B0 (io), 201 I/O11 B1 (io), 202 I/O12 B2 (io), 203 I/O13 B3 (io), 204 I/O14 B4 (io), 205 I/O15 B5 (io), 206 I/O16 B6 (io), 207 I/O17 B7 (io)
part B pins: 79 I/O78 XA1 (io), 80 I/O79 XA4 (io), 84 I/O80 XA6 (io), 85 I/O81 XA7 (io), 86 I/O82 XC0 (io), 87 I/O83 XC1 (io), 88 I/O84 XC2 (io), 89 I/O85 XC3 (io), 90 I/O86 XC4 (io), 91 I/O87 XC5 (io), 92 I/O88 XC6 (io), 93 I/O89 XC7 (io), 96 I/O90 XB0 (io), 97 I/O91 XB1 (io), 98 I/O92 XB2 (io), 99 I/O93 XB3 (io), 100 I/O94 XB4 (io), 101 I/O95 XB5 (io), 102 I/O96 XB6 (io), 103 I/O97 XB7 (io), 107 I/O98 XF7 (io), 108 I/O99 XF6 (io), 109 I/O100 XF5 (io), 110 I/O101 XF4 (io), 111 I/O102 XF3 (io), 112 I/O103 XF2 (io), 113 I/O104 XF1 (io), 114 I/O105 XF0 (io), 117 I/O106 XG7 (io), 118 I/O107 XG6 (io), 119 I/O108 XG5 (io), 120 I/O109 XG4 (io), 121 I/O110 XG3 (io), 122 I/O111 XG2 (io), 123 I/O112 XG1 (io), 124 I/O113 XG0 (io), 125 I/O114 XE7 (io), 126 I/O115 XE5 (io), 129 I/O116 XE2 (io), 130 I/O117 XE0 (io), 131 I/O118 XL0 (io), 132 I/O119 XL2 (io), 133 I/O120 XL3 (io), 135 I/O121 XL5 (io), 136 I/O122 XJ0 (io), 137 I/O123 XJ1 (io), 138 I/O124 XJ2 (io), 139 I/O125 XJ3 (io), 140 I/O126 XJ4 (io), 141 I/O127 XJ5 (io), 142 I/O128 XJ6 (io), 143 I/O129 XJ7 (io), 146 I/O130 XK0 (io), 147 I/O131 XK1 (io), 148 I/O132 XK2 (io), 149 I/O133 XK3 (io), 150 I/O134 XK4 (io), 151 I/O135 XK5 (io), 152 I/O136 XK6 (io), 153 I/O137 XK7 (io), 158 I/O138 XO7 (io), 159 I/O139 XO6 (io), 160 I/O140 XO5 (io), 161 I/O141 XO4 (io), 162 I/O142 XO3 (io), 163 I/O143 XO2 (io), 164 I/O144 XO1 (io), 165 I/O145 XO0 (io), 168 I/O146 XN7 (io), 169 I/O147 XN6 (io), 170 I/O148 XN5 (io), 171 I/O149 XN4 (io), 172 I/O150 XN3 (io), 173 I/O151 XN2 (io), 174 I/O152 XN1 (io), 175 I/O153 XN0 (io), 176 I/O154 XP7 (io), 177 I/O155 XP6 (io), 181 I/O156 XP4 (io), 182 I/O157 XP1 (io)
part C pins: 1 GND (power), 2 TDI (in), 11 VCC (power), 12 GND (power), 23 GND (power), 24 VCC (power), 30 GND (power), 40 GND (power), 41 VCC (power), 50 TMS (in), 51 TCK (in), 52 GND (power), 53 GND (power), 62 GND (power), 63 VCC (power), 74 CLK1 (in), 75 VCC (power), 76 GND (power), 81 GND (power), 82 VCC (power), 83 CLK2 (in), 94 VCC (power), 95 GND (power), 104 GND (power), 105 GND (power), 106 NC, 115 VCC (power), 116 GND (power), 127 GND (power), 128 VCC (power), 134 GND (power), 144 GND (power), 145 VCC (power), 154 NC, 155 TDO (out), 156 GND (power), 157 GND (power), 166 GND (power), 167 VCC (power), 178 CLK3 (in), 179 VCC (power), 180 GND (power), 185 GND (power), 186 VCC (power), 187 CLK0 (in), 198 VCC (power), 199 GND (power), 208 GND (power)

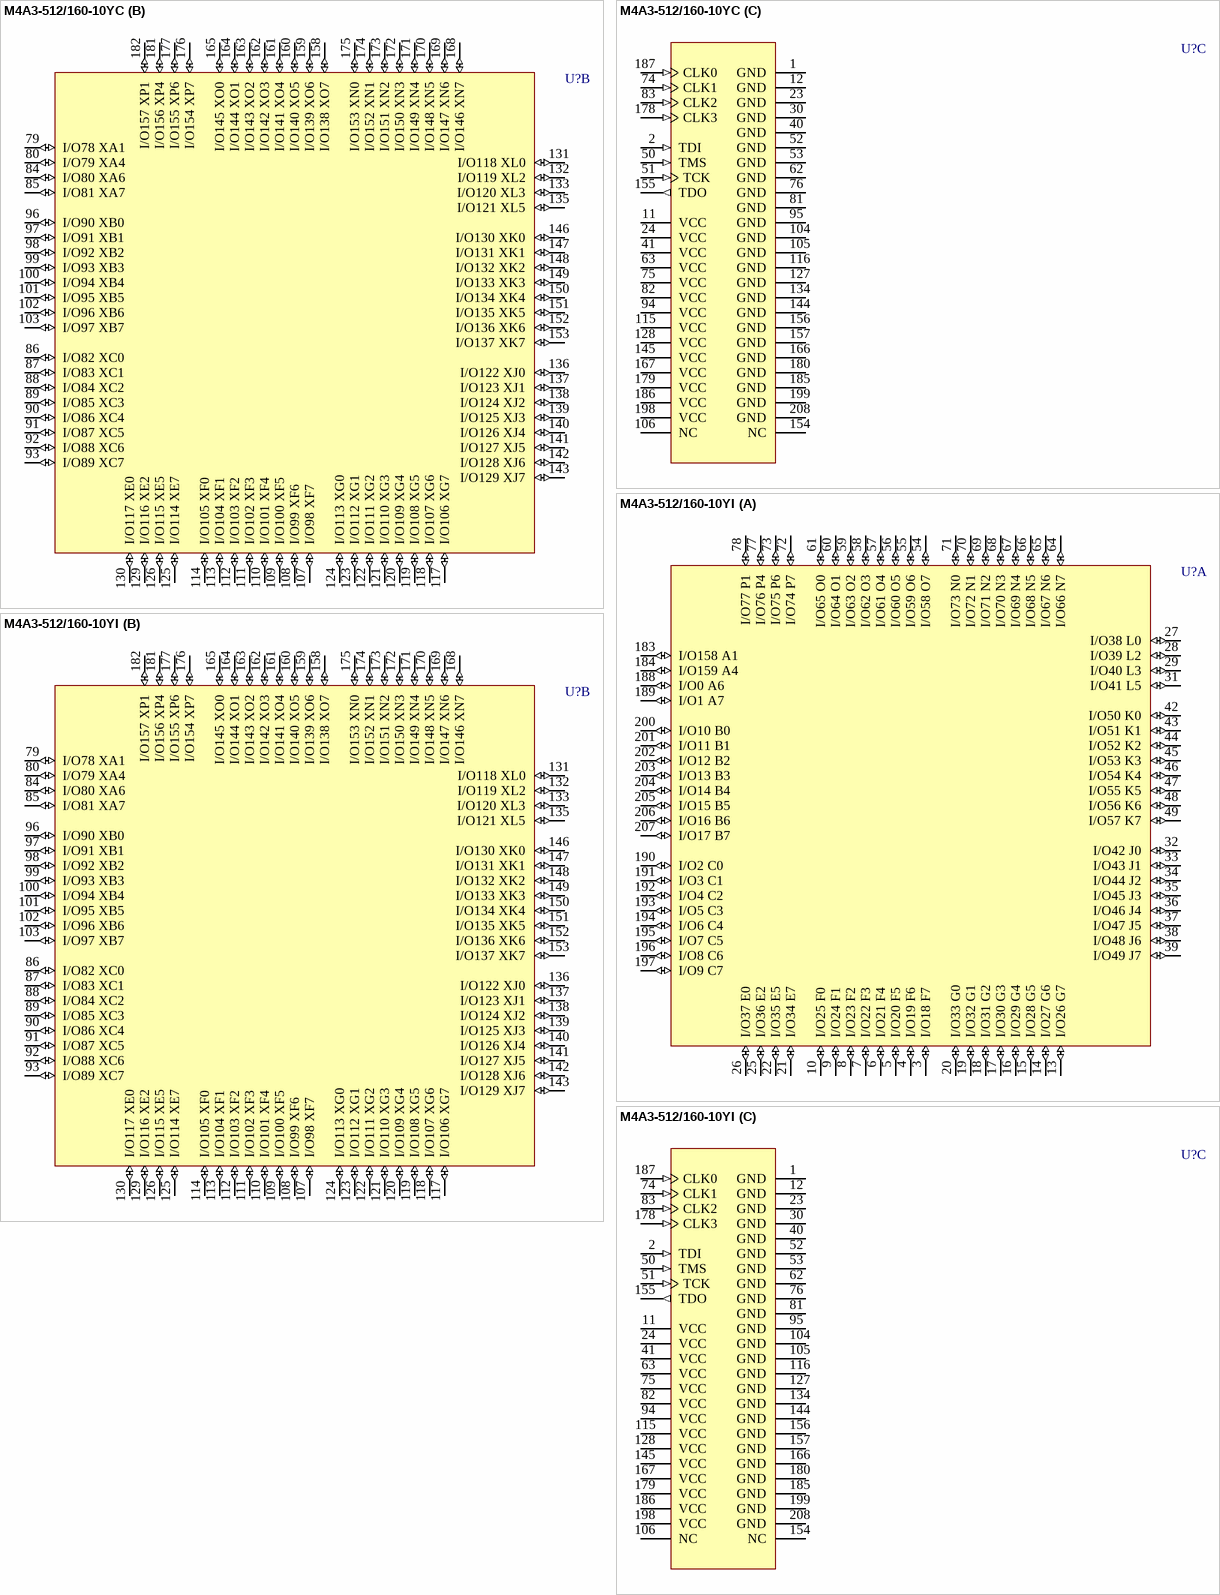
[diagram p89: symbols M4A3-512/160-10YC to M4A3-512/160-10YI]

## M4A3-512/160-10YC
designator U?
High-Performance EE CMOS In-System Programmable Logic
footprint PQFP208_N (Shrink QFP, 208-Leads, Body 28x28mm, Pitch 0.5mm, IPC Medium Density)
footprint PQFP208_L (Shrink QFP, 208-Leads, Body 28x28mm, Pitch 0.5mm, IPC High Density)
footprint PQFP208_M (Shrink QFP, 208-Leads, Body 28x28mm, Pitch 0.5mm, IPC Low Density)
3D model M4A3-PQFP208 (208-Pin Plastic Quad Flat Pack (PQFP208))
part A pins: 3 I/O18 F7 (io), 4 I/O19 F6 (io), 5 I/O20 F5 (io), 6 I/O21 F4 (io), 7 I/O22 F3 (io), 8 I/O23 F2 (io), 9 I/O24 F1 (io), 10 I/O25 F0 (io), 13 I/O26 G7 (io), 14 I/O27 G6 (io), 15 I/O28 G5 (io), 16 I/O29 G4 (io), 17 I/O30 G3 (io), 18 I/O31 G2 (io), 19 I/O32 G1 (io), 20 I/O33 G0 (io), 21 I/O34 E7 (io), 22 I/O35 E5 (io), 25 I/O36 E2 (io), 26 I/O37 E0 (io), 27 I/O38 L0 (io), 28 I/O39 L2 (io), 29 I/O40 L3 (io), 31 I/O41 L5 (io), 32 I/O42 J0 (io), 33 I/O43 J1 (io), 34 I/O44 J2 (io), 35 I/O45 J3 (io), 36 I/O46 J4 (io), 37 I/O47 J5 (io), 38 I/O48 J6 (io), 39 I/O49 J7 (io), 42 I/O50 K0 (io), 43 I/O51 K1 (io), 44 I/O52 K2 (io), 45 I/O53 K3 (io), 46 I/O54 K4 (io), 47 I/O55 K5 (io), 48 I/O56 K6 (io), 49 I/O57 K7 (io), 54 I/O58 O7 (io), 55 I/O59 O6 (io), 56 I/O60 O5 (io), 57 I/O61 O4 (io), 58 I/O62 O3 (io), 59 I/O63 O2 (io), 60 I/O64 O1 (io), 61 I/O65 O0 (io), 64 I/O66 N7 (io), 65 I/O67 N6 (io), 66 I/O68 N5 (io), 67 I/O69 N4 (io), 68 I/O70 N3 (io), 69 I/O71 N2 (io), 70 I/O72 N1 (io), 71 I/O73 N0 (io), 72 I/O74 P7 (io), 73 I/O75 P6 (io), 77 I/O76 P4 (io), 78 I/O77 P1 (io), 183 I/O158 A1 (io), 184 I/O159 A4 (io), 188 I/O0 A6 (io), 189 I/O1 A7 (io), 190 I/O2 C0 (io), 191 I/O3 C1 (io), 192 I/O4 C2 (io), 193 I/O5 C3 (io), 194 I/O6 C4 (io), 195 I/O7 C5 (io), 196 I/O8 C6 (io), 197 I/O9 C7 (io), 200 I/O10 B0 (io), 201 I/O11 B1 (io), 202 I/O12 B2 (io), 203 I/O13 B3 (io), 204 I/O14 B4 (io), 205 I/O15 B5 (io), 206 I/O16 B6 (io), 207 I/O17 B7 (io)
part B pins: 79 I/O78 XA1 (io), 80 I/O79 XA4 (io), 84 I/O80 XA6 (io), 85 I/O81 XA7 (io), 86 I/O82 XC0 (io), 87 I/O83 XC1 (io), 88 I/O84 XC2 (io), 89 I/O85 XC3 (io), 90 I/O86 XC4 (io), 91 I/O87 XC5 (io), 92 I/O88 XC6 (io), 93 I/O89 XC7 (io), 96 I/O90 XB0 (io), 97 I/O91 XB1 (io), 98 I/O92 XB2 (io), 99 I/O93 XB3 (io), 100 I/O94 XB4 (io), 101 I/O95 XB5 (io), 102 I/O96 XB6 (io), 103 I/O97 XB7 (io), 107 I/O98 XF7 (io), 108 I/O99 XF6 (io), 109 I/O100 XF5 (io), 110 I/O101 XF4 (io), 111 I/O102 XF3 (io), 112 I/O103 XF2 (io), 113 I/O104 XF1 (io), 114 I/O105 XF0 (io), 117 I/O106 XG7 (io), 118 I/O107 XG6 (io), 119 I/O108 XG5 (io), 120 I/O109 XG4 (io), 121 I/O110 XG3 (io), 122 I/O111 XG2 (io), 123 I/O112 XG1 (io), 124 I/O113 XG0 (io), 125 I/O114 XE7 (io), 126 I/O115 XE5 (io), 129 I/O116 XE2 (io), 130 I/O117 XE0 (io), 131 I/O118 XL0 (io), 132 I/O119 XL2 (io), 133 I/O120 XL3 (io), 135 I/O121 XL5 (io), 136 I/O122 XJ0 (io), 137 I/O123 XJ1 (io), 138 I/O124 XJ2 (io), 139 I/O125 XJ3 (io), 140 I/O126 XJ4 (io), 141 I/O127 XJ5 (io), 142 I/O128 XJ6 (io), 143 I/O129 XJ7 (io), 146 I/O130 XK0 (io), 147 I/O131 XK1 (io), 148 I/O132 XK2 (io), 149 I/O133 XK3 (io), 150 I/O134 XK4 (io), 151 I/O135 XK5 (io), 152 I/O136 XK6 (io), 153 I/O137 XK7 (io), 158 I/O138 XO7 (io), 159 I/O139 XO6 (io), 160 I/O140 XO5 (io), 161 I/O141 XO4 (io), 162 I/O142 XO3 (io), 163 I/O143 XO2 (io), 164 I/O144 XO1 (io), 165 I/O145 XO0 (io), 168 I/O146 XN7 (io), 169 I/O147 XN6 (io), 170 I/O148 XN5 (io), 171 I/O149 XN4 (io), 172 I/O150 XN3 (io), 173 I/O151 XN2 (io), 174 I/O152 XN1 (io), 175 I/O153 XN0 (io), 176 I/O154 XP7 (io), 177 I/O155 XP6 (io), 181 I/O156 XP4 (io), 182 I/O157 XP1 (io)
part C pins: 1 GND (power), 2 TDI (in), 11 VCC (power), 12 GND (power), 23 GND (power), 24 VCC (power), 30 GND (power), 40 GND (power), 41 VCC (power), 50 TMS (in), 51 TCK (in), 52 GND (power), 53 GND (power), 62 GND (power), 63 VCC (power), 74 CLK1 (in), 75 VCC (power), 76 GND (power), 81 GND (power), 82 VCC (power), 83 CLK2 (in), 94 VCC (power), 95 GND (power), 104 GND (power), 105 GND (power), 106 NC, 115 VCC (power), 116 GND (power), 127 GND (power), 128 VCC (power), 134 GND (power), 144 GND (power), 145 VCC (power), 154 NC, 155 TDO (out), 156 GND (power), 157 GND (power), 166 GND (power), 167 VCC (power), 178 CLK3 (in), 179 VCC (power), 180 GND (power), 185 GND (power), 186 VCC (power), 187 CLK0 (in), 198 VCC (power), 199 GND (power), 208 GND (power)

## M4A3-512/160-10YI
designator U?
High-Performance EE CMOS In-System Programmable Logic
footprint PQFP208_N (Shrink QFP, 208-Leads, Body 28x28mm, Pitch 0.5mm, IPC Medium Density)
footprint PQFP208_L (Shrink QFP, 208-Leads, Body 28x28mm, Pitch 0.5mm, IPC High Density)
footprint PQFP208_M (Shrink QFP, 208-Leads, Body 28x28mm, Pitch 0.5mm, IPC Low Density)
3D model M4A3-PQFP208 (208-Pin Plastic Quad Flat Pack (PQFP208))
part A pins: 3 I/O18 F7 (io), 4 I/O19 F6 (io), 5 I/O20 F5 (io), 6 I/O21 F4 (io), 7 I/O22 F3 (io), 8 I/O23 F2 (io), 9 I/O24 F1 (io), 10 I/O25 F0 (io), 13 I/O26 G7 (io), 14 I/O27 G6 (io), 15 I/O28 G5 (io), 16 I/O29 G4 (io), 17 I/O30 G3 (io), 18 I/O31 G2 (io), 19 I/O32 G1 (io), 20 I/O33 G0 (io), 21 I/O34 E7 (io), 22 I/O35 E5 (io), 25 I/O36 E2 (io), 26 I/O37 E0 (io), 27 I/O38 L0 (io), 28 I/O39 L2 (io), 29 I/O40 L3 (io), 31 I/O41 L5 (io), 32 I/O42 J0 (io), 33 I/O43 J1 (io), 34 I/O44 J2 (io), 35 I/O45 J3 (io), 36 I/O46 J4 (io), 37 I/O47 J5 (io), 38 I/O48 J6 (io), 39 I/O49 J7 (io), 42 I/O50 K0 (io), 43 I/O51 K1 (io), 44 I/O52 K2 (io), 45 I/O53 K3 (io), 46 I/O54 K4 (io), 47 I/O55 K5 (io), 48 I/O56 K6 (io), 49 I/O57 K7 (io), 54 I/O58 O7 (io), 55 I/O59 O6 (io), 56 I/O60 O5 (io), 57 I/O61 O4 (io), 58 I/O62 O3 (io), 59 I/O63 O2 (io), 60 I/O64 O1 (io), 61 I/O65 O0 (io), 64 I/O66 N7 (io), 65 I/O67 N6 (io), 66 I/O68 N5 (io), 67 I/O69 N4 (io), 68 I/O70 N3 (io), 69 I/O71 N2 (io), 70 I/O72 N1 (io), 71 I/O73 N0 (io), 72 I/O74 P7 (io), 73 I/O75 P6 (io), 77 I/O76 P4 (io), 78 I/O77 P1 (io), 183 I/O158 A1 (io), 184 I/O159 A4 (io), 188 I/O0 A6 (io), 189 I/O1 A7 (io), 190 I/O2 C0 (io), 191 I/O3 C1 (io), 192 I/O4 C2 (io), 193 I/O5 C3 (io), 194 I/O6 C4 (io), 195 I/O7 C5 (io), 196 I/O8 C6 (io), 197 I/O9 C7 (io), 200 I/O10 B0 (io), 201 I/O11 B1 (io), 202 I/O12 B2 (io), 203 I/O13 B3 (io), 204 I/O14 B4 (io), 205 I/O15 B5 (io), 206 I/O16 B6 (io), 207 I/O17 B7 (io)
part B pins: 79 I/O78 XA1 (io), 80 I/O79 XA4 (io), 84 I/O80 XA6 (io), 85 I/O81 XA7 (io), 86 I/O82 XC0 (io), 87 I/O83 XC1 (io), 88 I/O84 XC2 (io), 89 I/O85 XC3 (io), 90 I/O86 XC4 (io), 91 I/O87 XC5 (io), 92 I/O88 XC6 (io), 93 I/O89 XC7 (io), 96 I/O90 XB0 (io), 97 I/O91 XB1 (io), 98 I/O92 XB2 (io), 99 I/O93 XB3 (io), 100 I/O94 XB4 (io), 101 I/O95 XB5 (io), 102 I/O96 XB6 (io), 103 I/O97 XB7 (io), 107 I/O98 XF7 (io), 108 I/O99 XF6 (io), 109 I/O100 XF5 (io), 110 I/O101 XF4 (io), 111 I/O102 XF3 (io), 112 I/O103 XF2 (io), 113 I/O104 XF1 (io), 114 I/O105 XF0 (io), 117 I/O106 XG7 (io), 118 I/O107 XG6 (io), 119 I/O108 XG5 (io), 120 I/O109 XG4 (io), 121 I/O110 XG3 (io), 122 I/O111 XG2 (io), 123 I/O112 XG1 (io), 124 I/O113 XG0 (io), 125 I/O114 XE7 (io), 126 I/O115 XE5 (io), 129 I/O116 XE2 (io), 130 I/O117 XE0 (io), 131 I/O118 XL0 (io), 132 I/O119 XL2 (io), 133 I/O120 XL3 (io), 135 I/O121 XL5 (io), 136 I/O122 XJ0 (io), 137 I/O123 XJ1 (io), 138 I/O124 XJ2 (io), 139 I/O125 XJ3 (io), 140 I/O126 XJ4 (io), 141 I/O127 XJ5 (io), 142 I/O128 XJ6 (io), 143 I/O129 XJ7 (io), 146 I/O130 XK0 (io), 147 I/O131 XK1 (io), 148 I/O132 XK2 (io), 149 I/O133 XK3 (io), 150 I/O134 XK4 (io), 151 I/O135 XK5 (io), 152 I/O136 XK6 (io), 153 I/O137 XK7 (io), 158 I/O138 XO7 (io), 159 I/O139 XO6 (io), 160 I/O140 XO5 (io), 161 I/O141 XO4 (io), 162 I/O142 XO3 (io), 163 I/O143 XO2 (io), 164 I/O144 XO1 (io), 165 I/O145 XO0 (io), 168 I/O146 XN7 (io), 169 I/O147 XN6 (io), 170 I/O148 XN5 (io), 171 I/O149 XN4 (io), 172 I/O150 XN3 (io), 173 I/O151 XN2 (io), 174 I/O152 XN1 (io), 175 I/O153 XN0 (io), 176 I/O154 XP7 (io), 177 I/O155 XP6 (io), 181 I/O156 XP4 (io), 182 I/O157 XP1 (io)
part C pins: 1 GND (power), 2 TDI (in), 11 VCC (power), 12 GND (power), 23 GND (power), 24 VCC (power), 30 GND (power), 40 GND (power), 41 VCC (power), 50 TMS (in), 51 TCK (in), 52 GND (power), 53 GND (power), 62 GND (power), 63 VCC (power), 74 CLK1 (in), 75 VCC (power), 76 GND (power), 81 GND (power), 82 VCC (power), 83 CLK2 (in), 94 VCC (power), 95 GND (power), 104 GND (power), 105 GND (power), 106 NC, 115 VCC (power), 116 GND (power), 127 GND (power), 128 VCC (power), 134 GND (power), 144 GND (power), 145 VCC (power), 154 NC, 155 TDO (out), 156 GND (power), 157 GND (power), 166 GND (power), 167 VCC (power), 178 CLK3 (in), 179 VCC (power), 180 GND (power), 185 GND (power), 186 VCC (power), 187 CLK0 (in), 198 VCC (power), 199 GND (power), 208 GND (power)

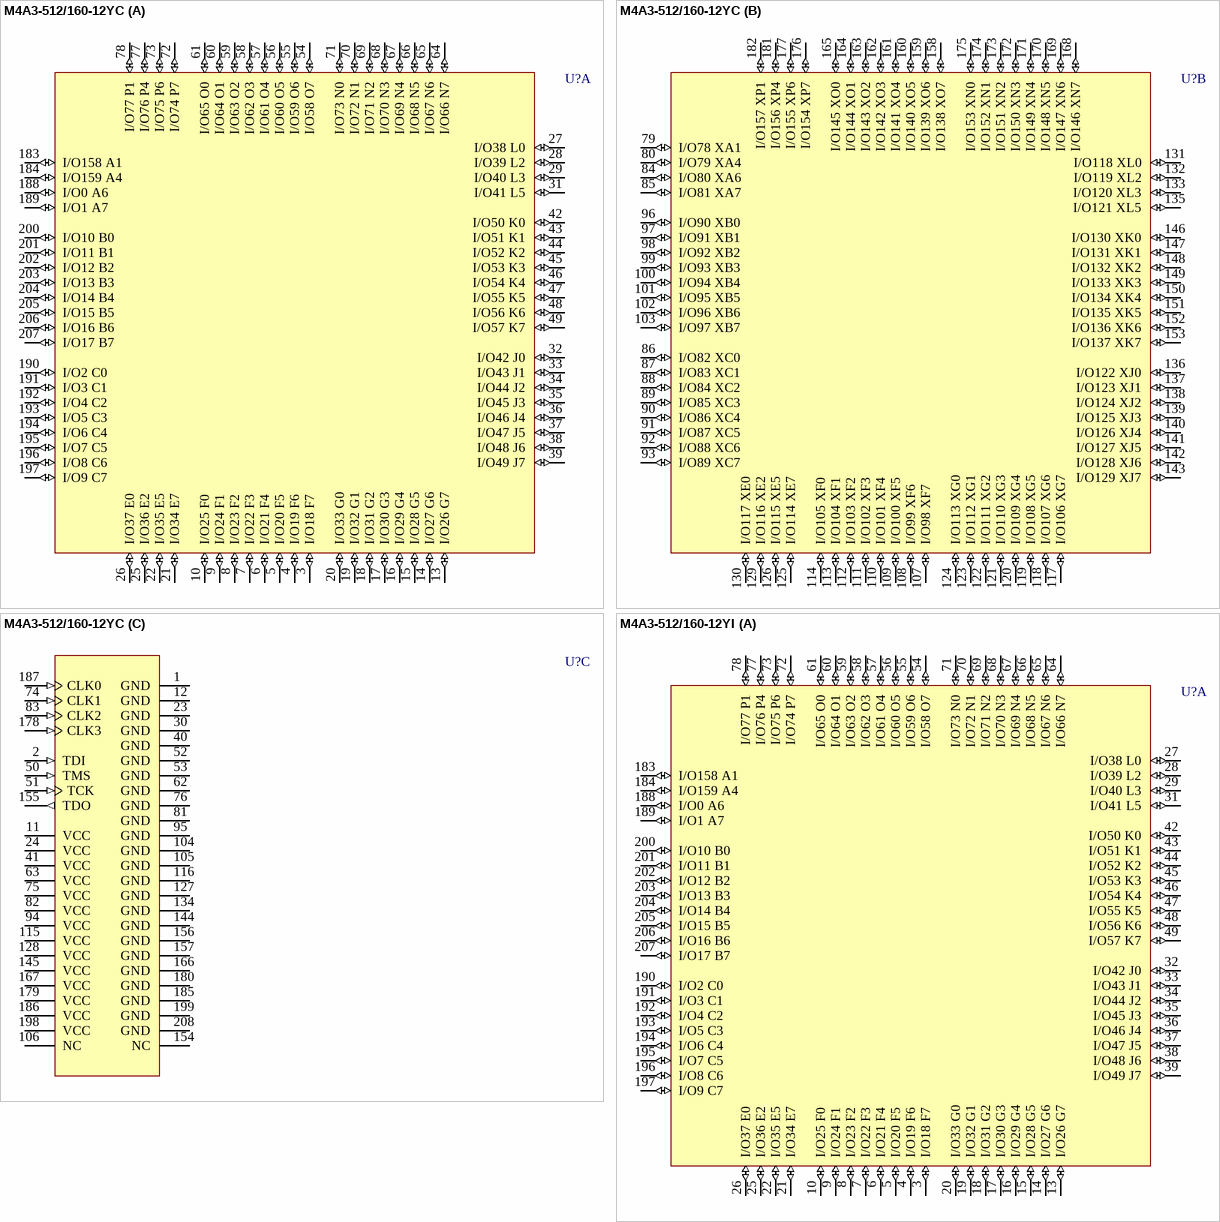
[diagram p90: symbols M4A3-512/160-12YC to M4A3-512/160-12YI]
